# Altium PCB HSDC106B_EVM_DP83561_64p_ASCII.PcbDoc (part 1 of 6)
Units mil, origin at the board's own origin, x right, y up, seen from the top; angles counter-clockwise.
Board outline 8750.24 x 6394.7 mil, 6 copper layers (Top Layer, GND, SIG1, SIG2, GND1, Bottom Layer), stack 60.4 mil thick; 475 components, 330 nets, 1628 pads, 1086 vias.
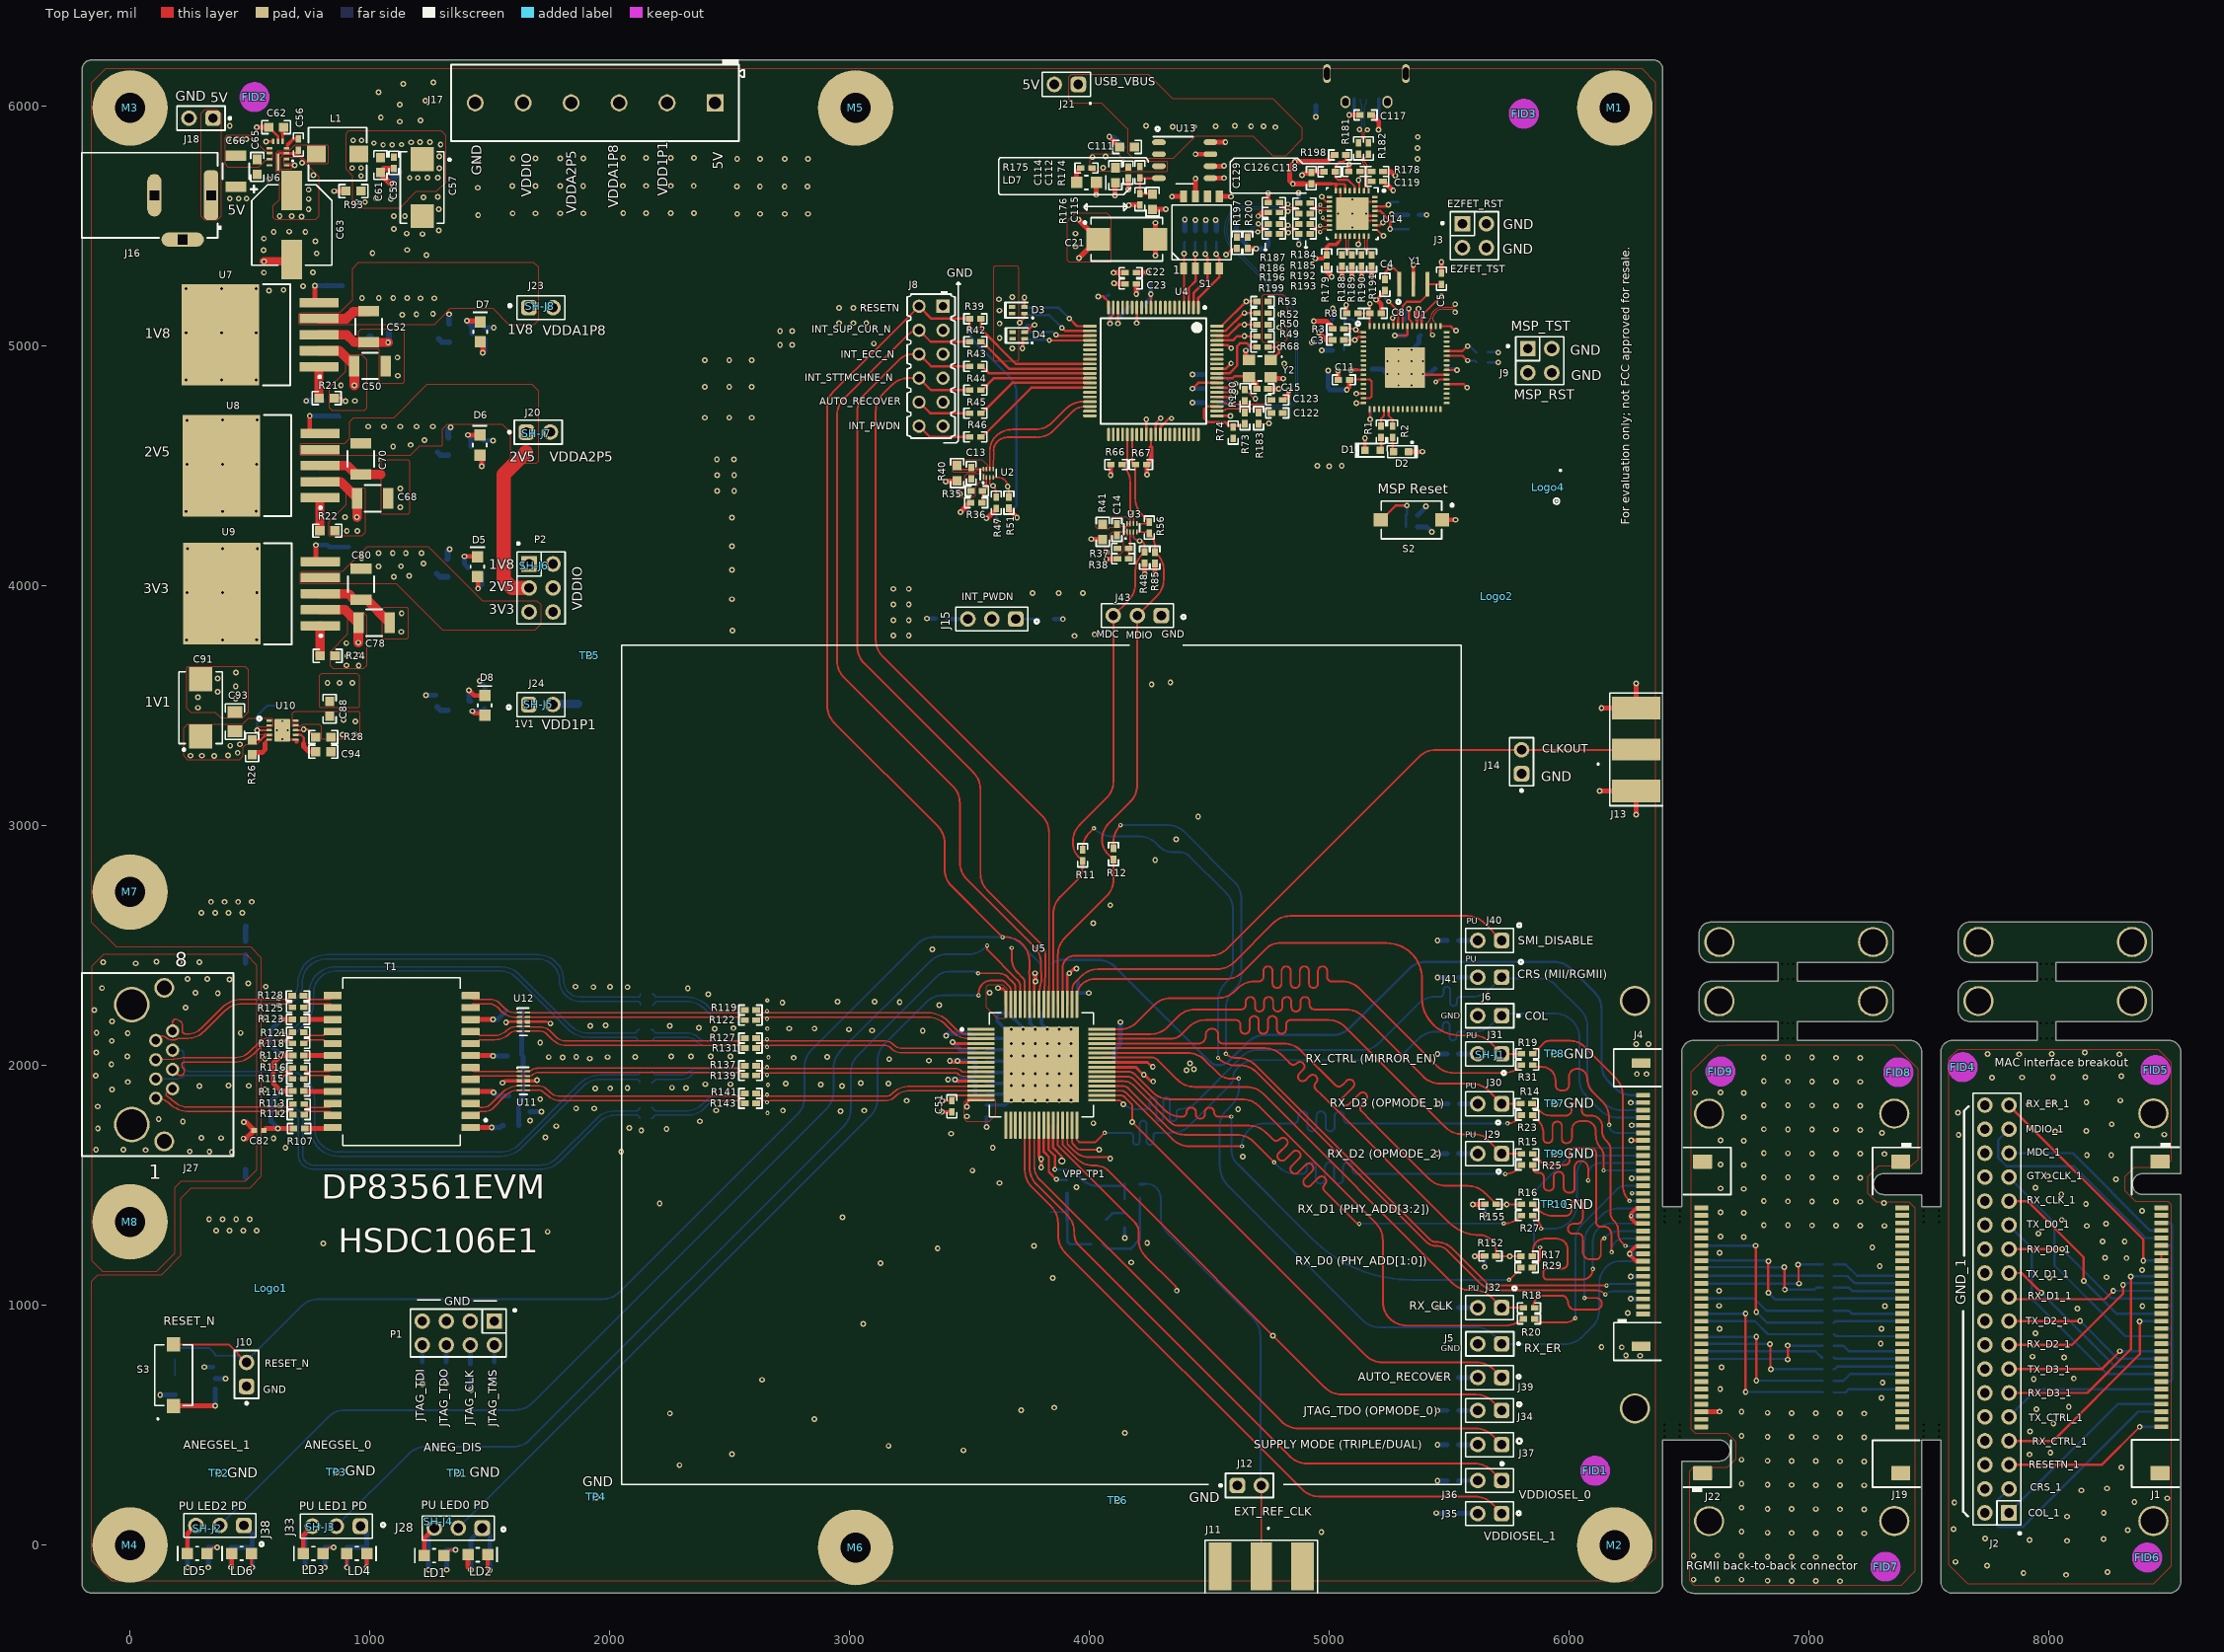
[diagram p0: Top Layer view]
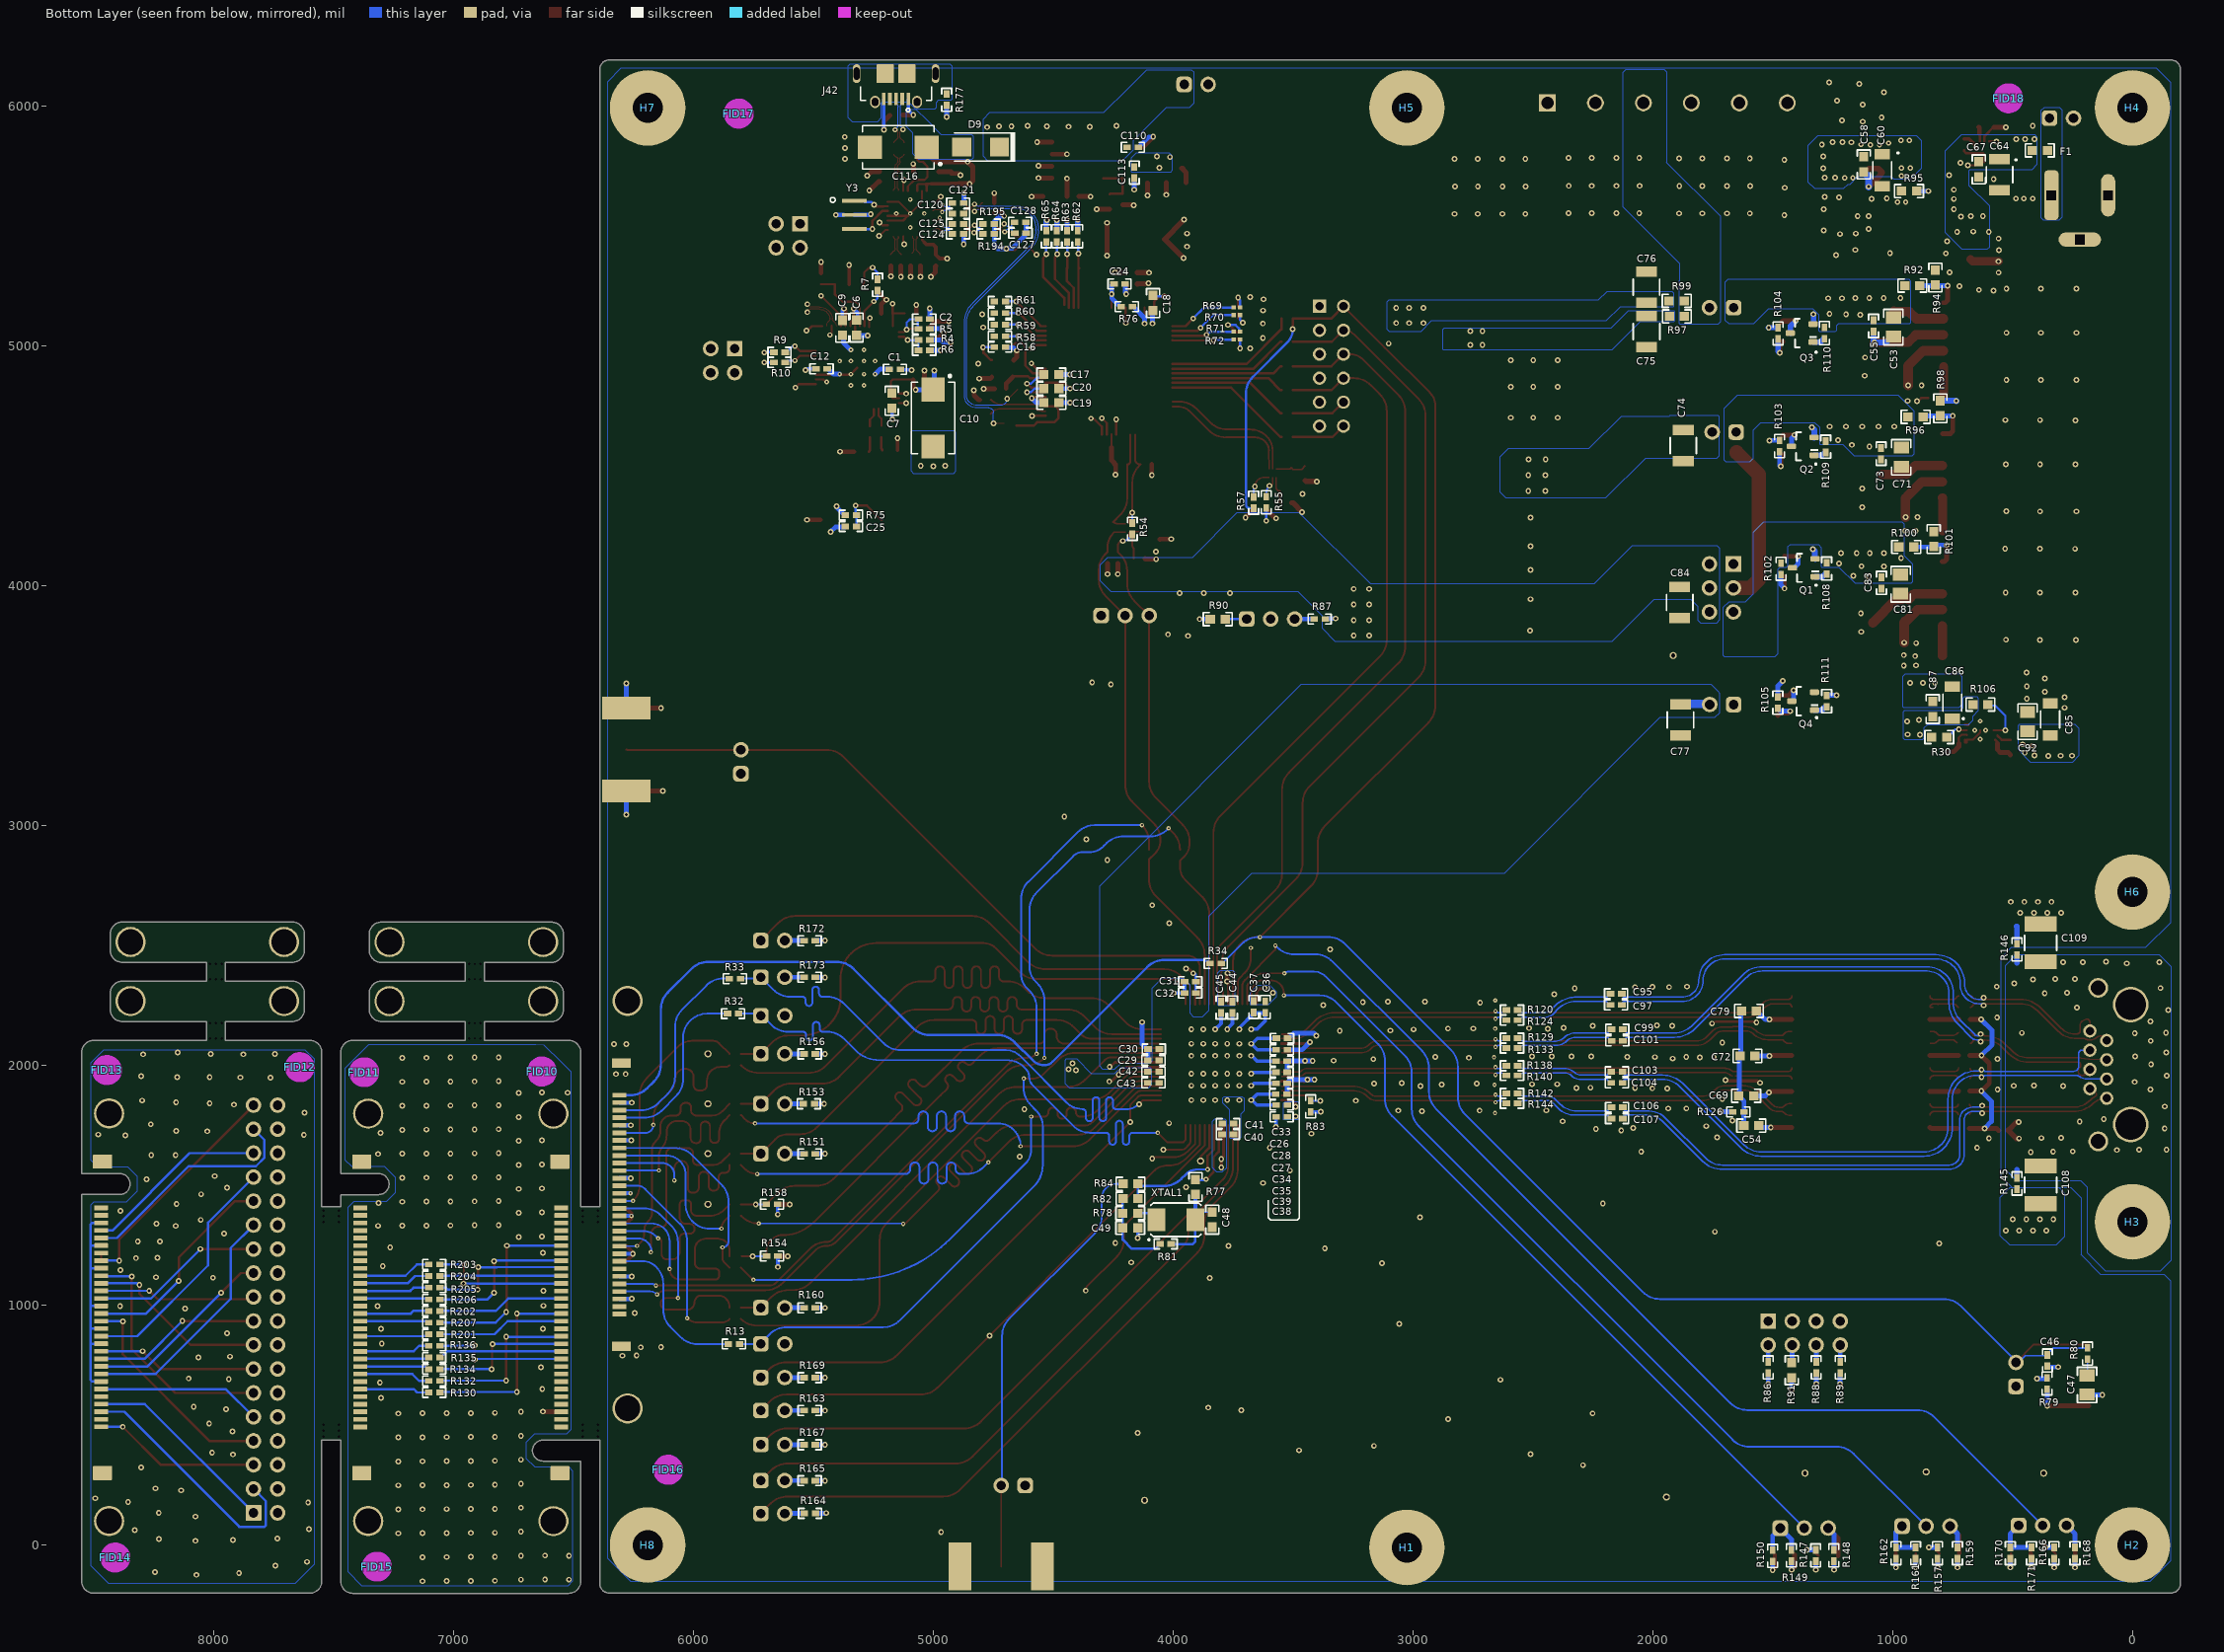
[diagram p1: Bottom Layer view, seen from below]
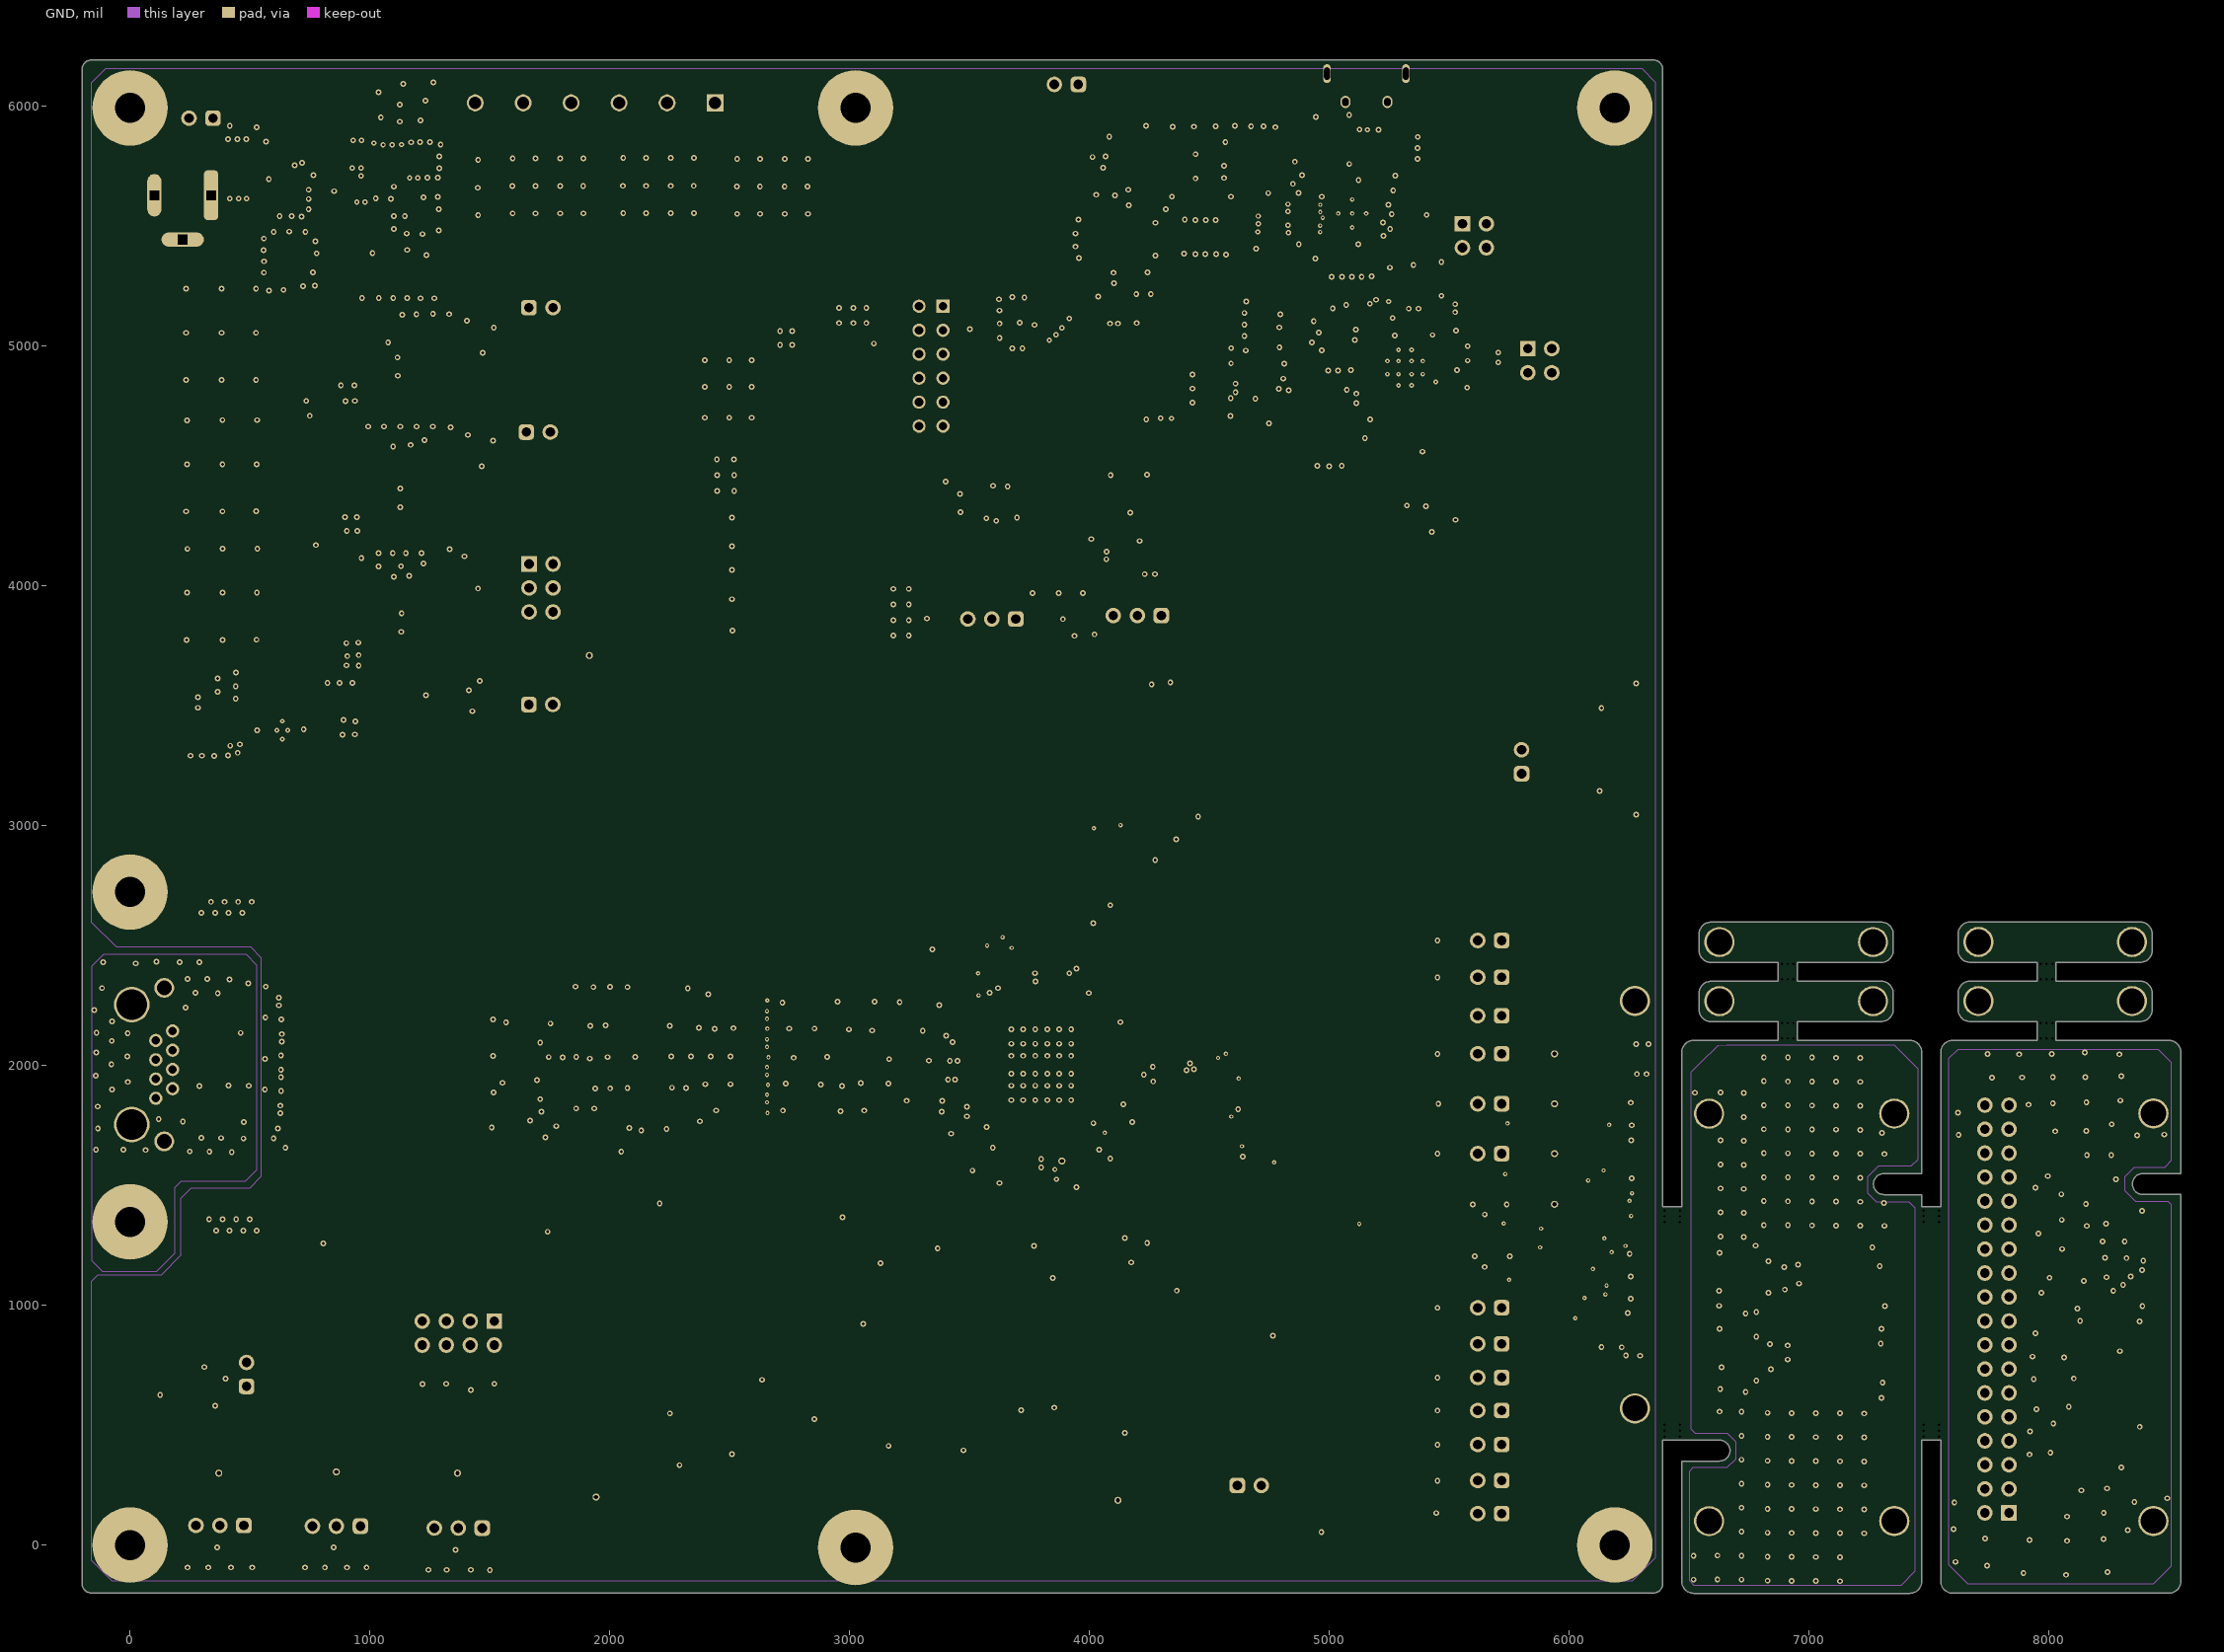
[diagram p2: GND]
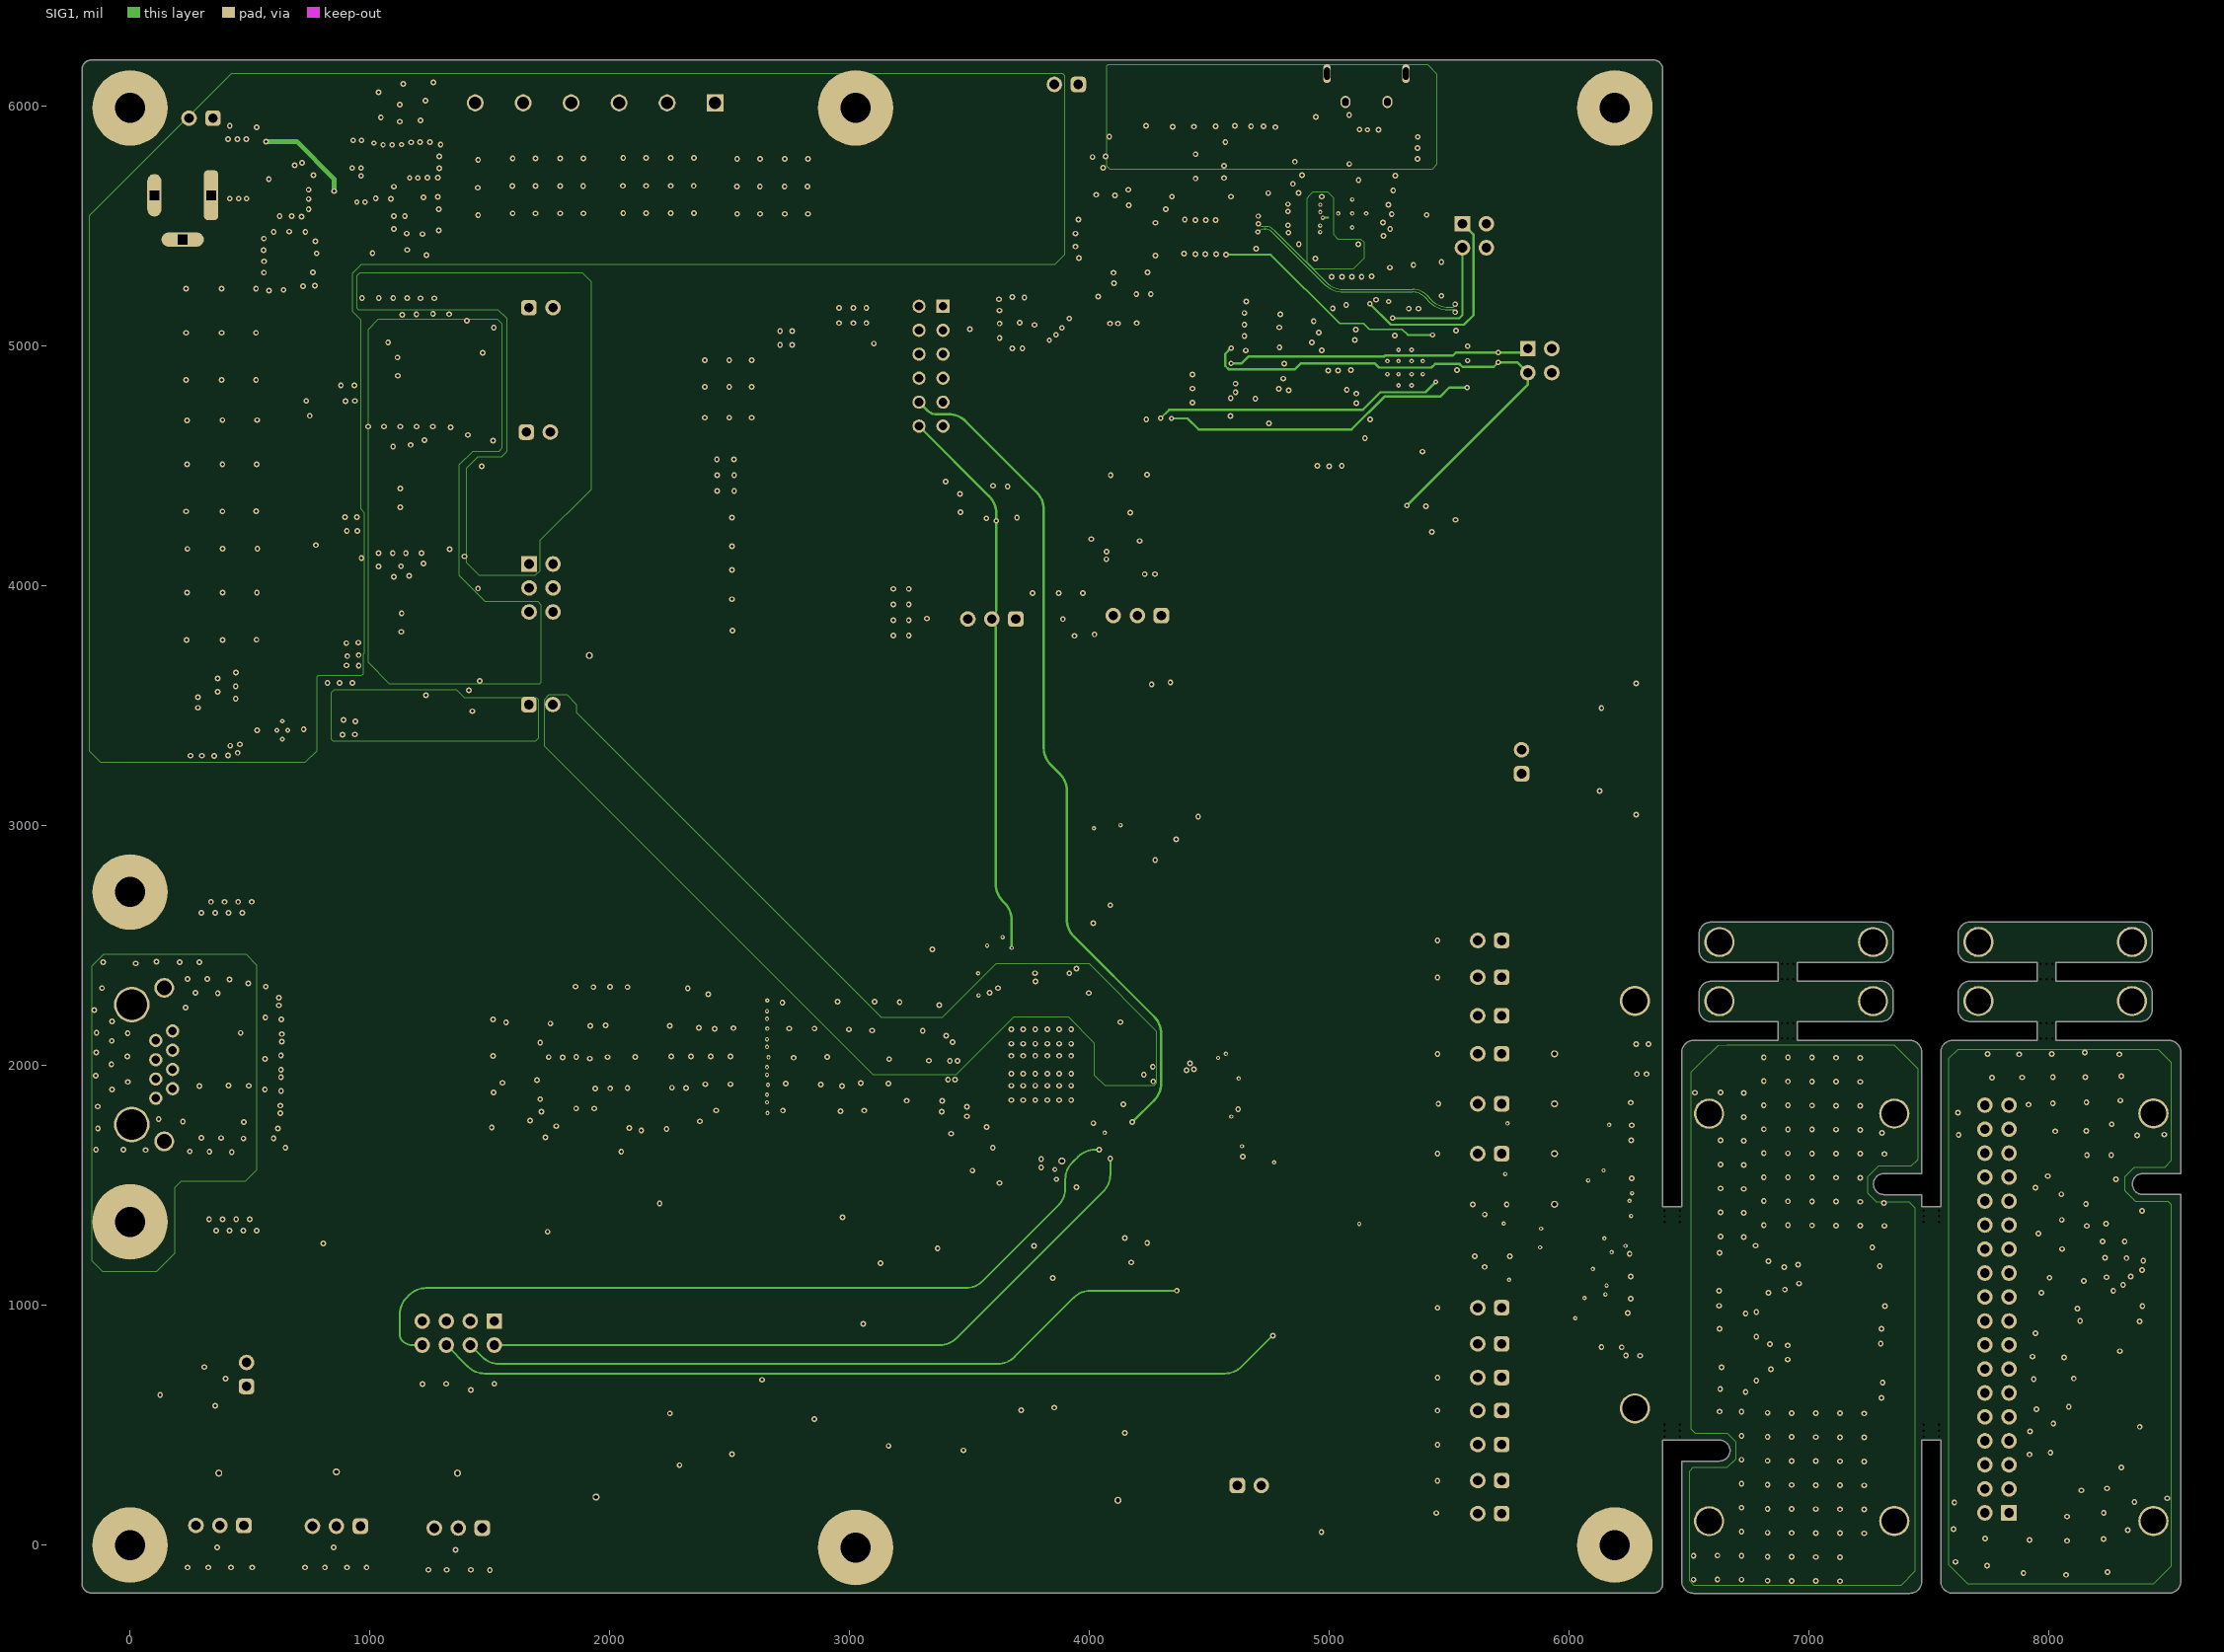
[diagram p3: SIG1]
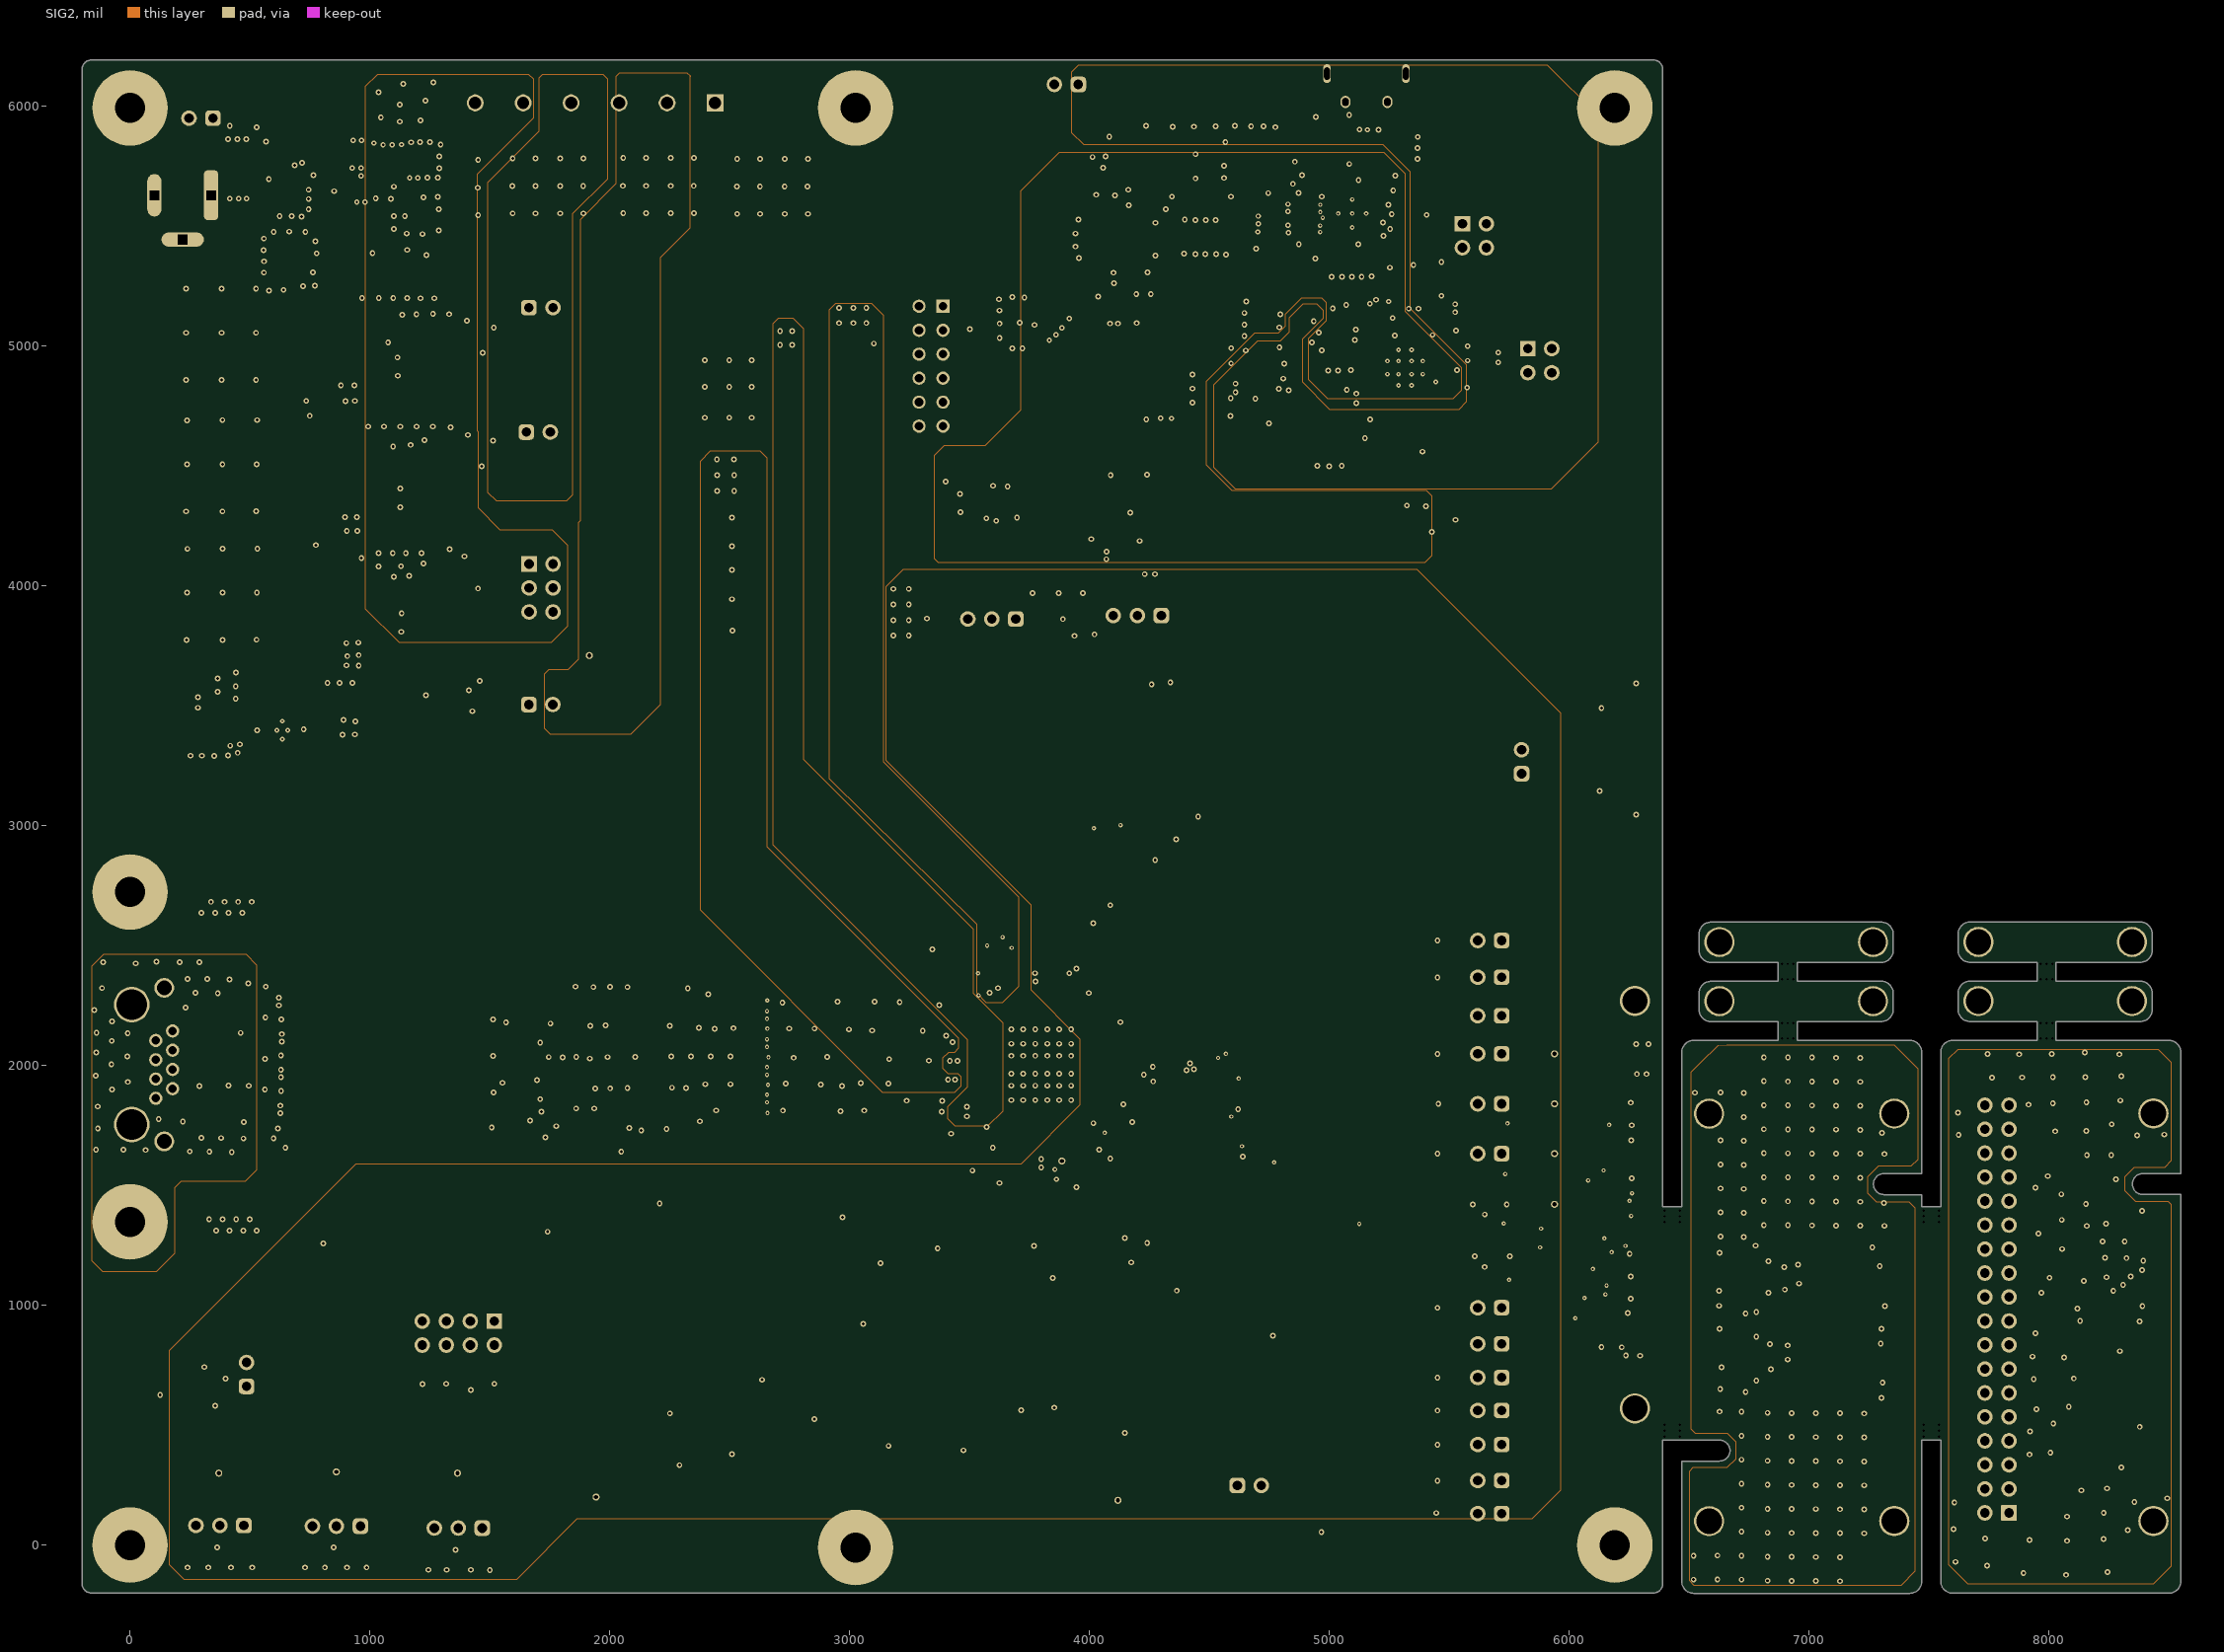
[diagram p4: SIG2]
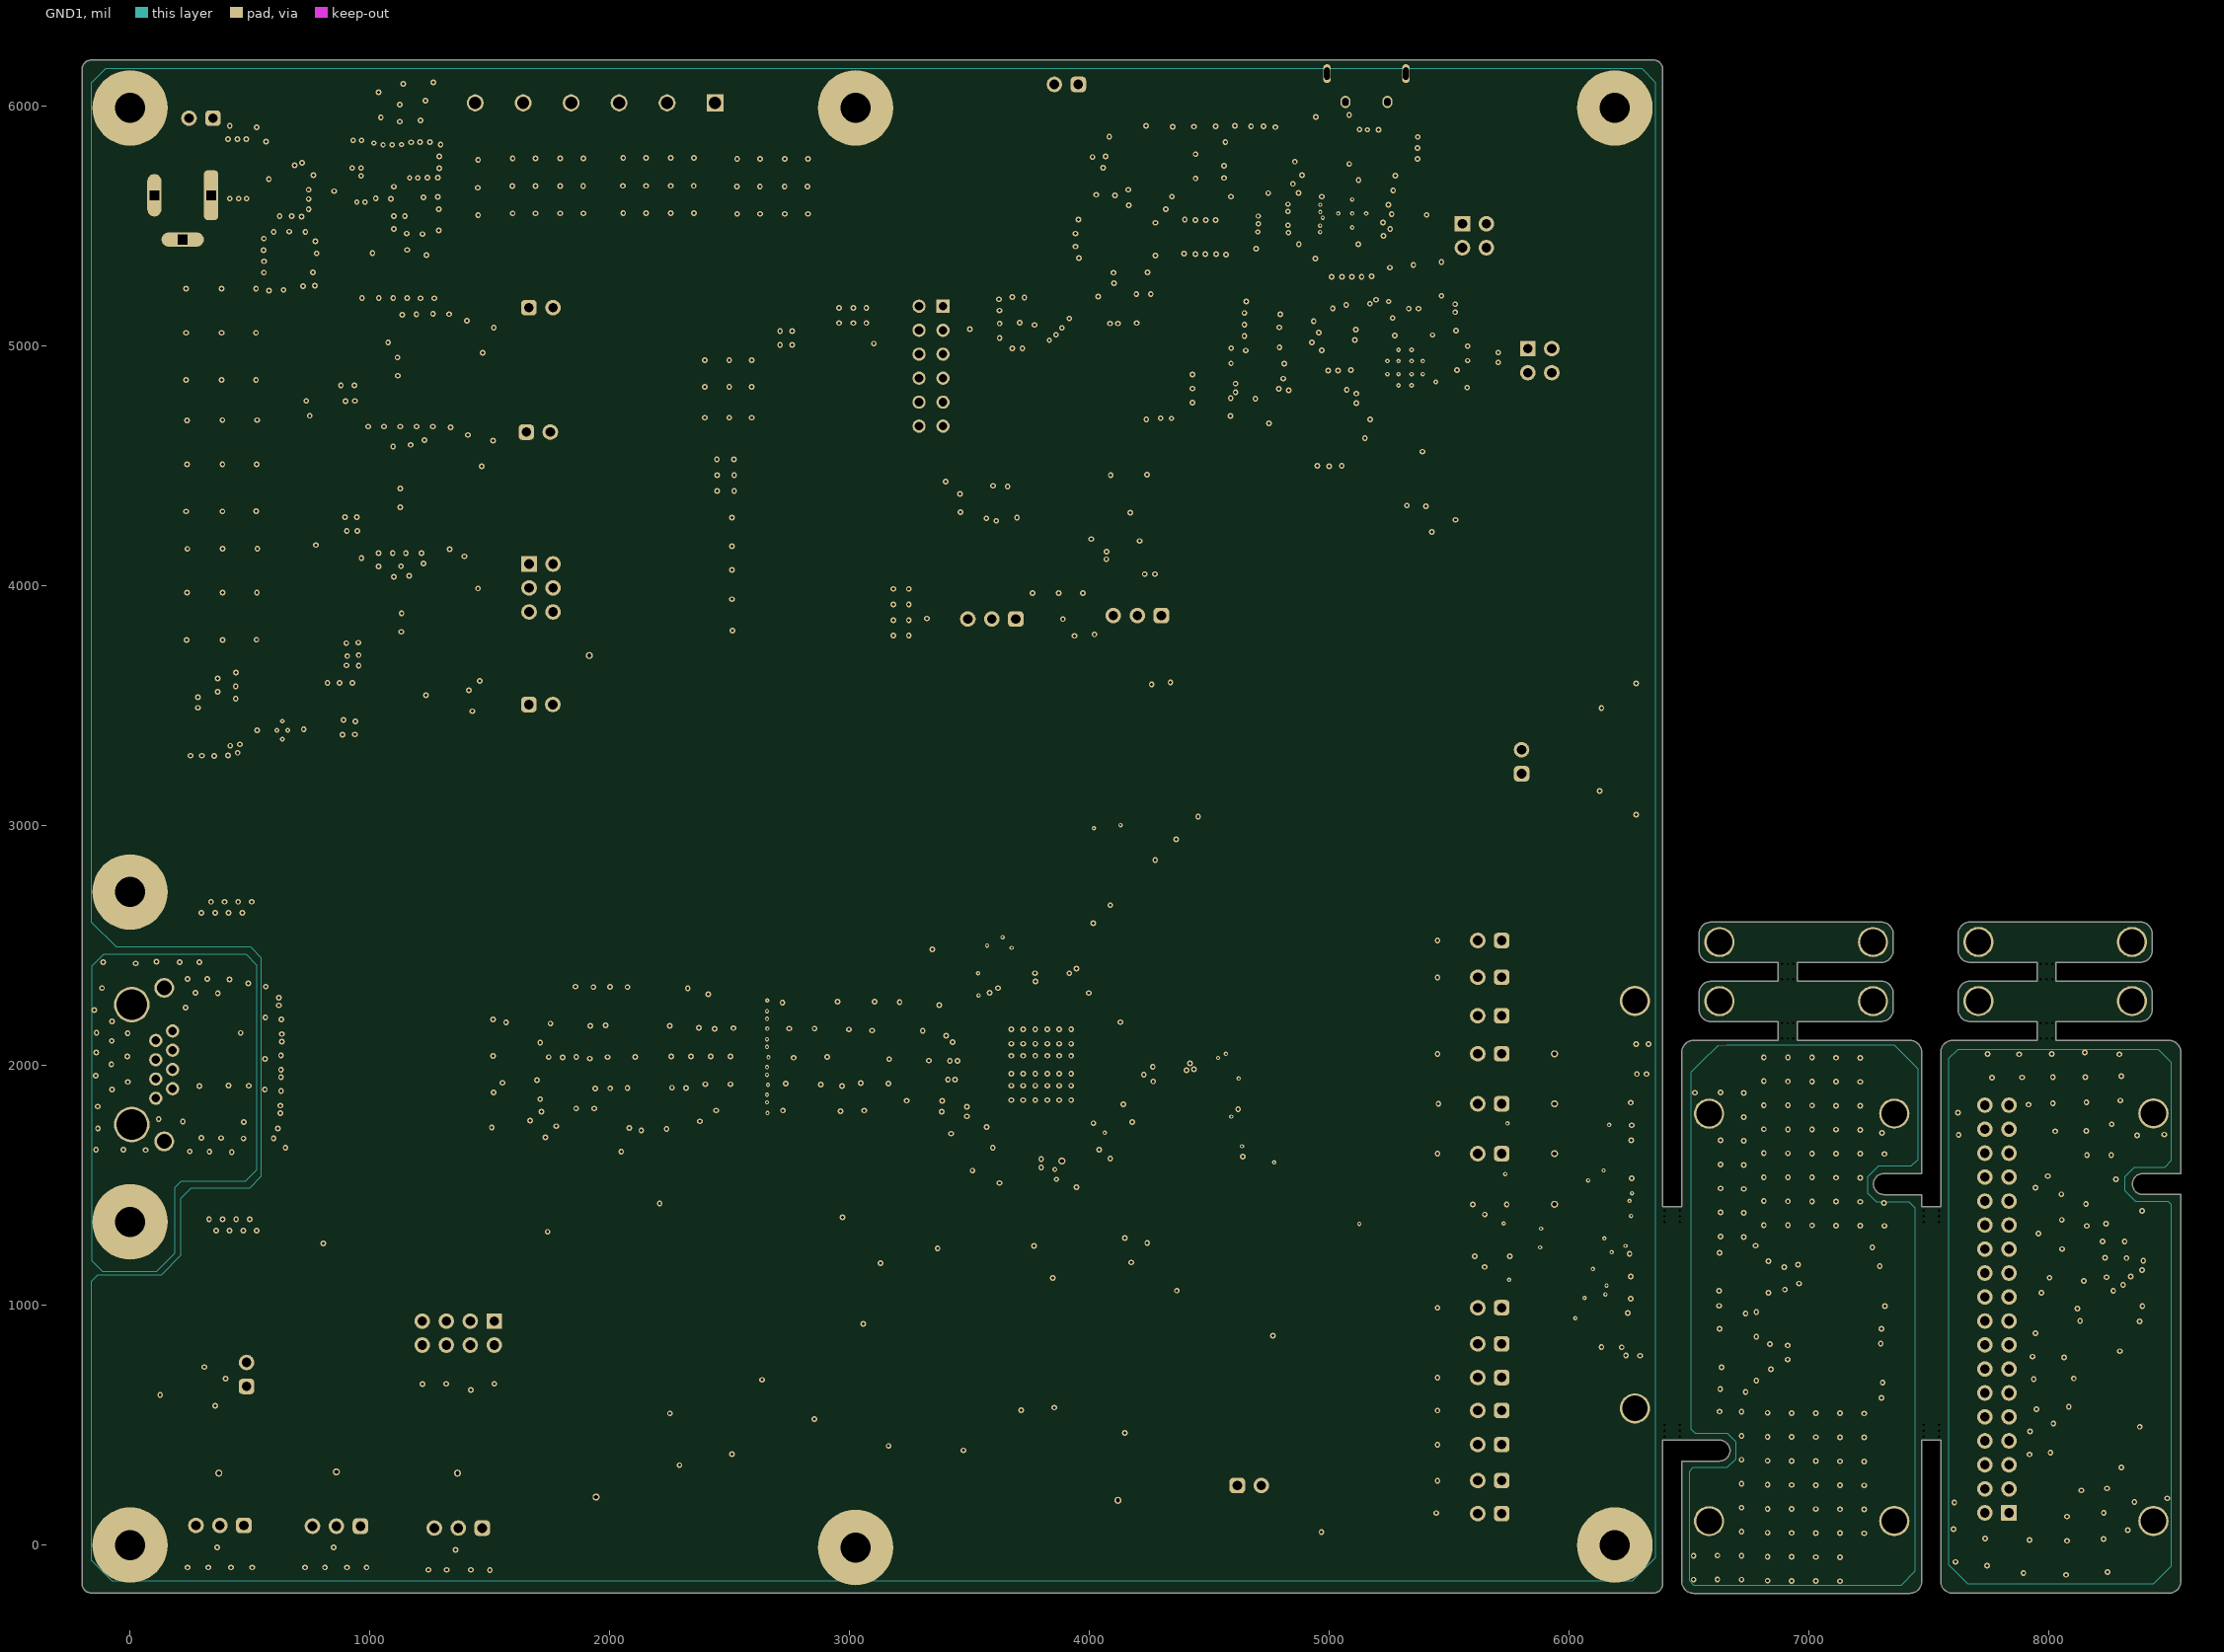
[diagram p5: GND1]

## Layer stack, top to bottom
Top Solder: solder mask 0.7, Solder Resist, Dk 3.5
Top Layer: signal copper 1.4
Dielectric 1: prepreg 5, FR-4 High Tg, Dk 4.6
GND: signal copper 1.4
Dielectric  2: core 5, FR-4 High Tg, Dk 4.6
SIG1: signal copper 1.4
Dielectric 3: prepreg 32, FR-4 High Tg, Dk 4.6
SIG2: signal copper 1.4
Dielectric 4: core 5, FR-4 High Tg, Dk 4.6
GND1: signal copper 1.4
Dielectric 5: prepreg 5, FR-4 High Tg, Dk 4.6
Bottom Layer: signal copper 1.4
Bottom Solder: solder mask 0.7, Solder Resist, Dk 3.5

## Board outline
6350.55,-200 ccw(c6350.55,-160) 6390.55,-160 6390.55,437.61 6391.84,437.8 6627.15,437.8 cw(c6627.15,394.35) 6670.6,394.35 6670.6,393.93 cw(c6627.06,393.93) 6627.06,350.39 6469.58,350.39 6469.29,297.49 6469.29,-151 ccw(c6519.29,-151) 6519.29,-201 7420.39,-201 ccw(c7420.39,-151) 7470.39,-151 7470.39,438.1 7549.42,438.1 7549.42,350.7 7549.13,297.8 7549.13,-150.69 ccw(c7599.13,-150.69) 7599.13,-200.69 8500.24,-200.69 ccw(c8500.24,-150.69) 8550.24,-150.69 8550.24,1462.03 8391.97,1462.03 cw(c8391.97,1505.48) 8348.52,1505.48 8348.52,1505.89 cw(c8392.06,1505.89) 8392.06,1549.43 8550.24,1549.43 8550.24,2054.91 ccw(c8500.24,2054.91) 8500.24,2104.91 8030.39,2104.91 8030.39,2183.65 8380.97,2183.65 8380.97,2183.78 ccw(c8380.97,2233.78) 8430.97,2233.78 8430.97,2301.78 ccw(c8380.97,2301.78) 8380.97,2351.78 8380.84,2351.65 8030.39,2351.65 8030.39,2430.39 8380.97,2430.39 8380.97,2430.52 ccw(c8380.97,2480.52) 8430.97,2480.52 8430.97,2548.52 ccw(c8380.97,2548.52) 8380.97,2598.52 8380.84,2598.39 7671.68,2598.39 ccw(c7671.68,2548.39) 7621.68,2548.39 7621.68,2480.39 ccw(c7671.68,2480.39) 7671.68,2430.39 7951.65,2430.39 7951.65,2351.65 7671.68,2351.65 ccw(c7671.68,2301.65) 7621.68,2301.65 7621.68,2233.65 ccw(c7671.68,2233.65) 7671.68,2183.65 7951.65,2183.65 7951.65,2104.91 7599.13,2104.91 ccw(c7599.13,2054.91) 7549.13,2054.91 7549.13,1410.74 7470.39,1410.74 7470.39,1461.72 7312.13,1461.72 cw(c7312.13,1505.17) 7268.68,1505.17 7268.68,1505.59 cw(c7312.22,1505.59) 7312.22,1549.13 7470.39,1549.13 7470.39,2054.61 ccw(c7420.39,2054.61) 7420.39,2104.61 6950.55,2104.61 6950.55,2183.35 7301.13,2183.35 7301.13,2183.47 ccw(c7301.13,2233.47) 7351.13,2233.47 7351.13,2301.47 ccw(c7301.13,2301.47) 7301.13,2351.47 7301,2351.35 6950.55,2351.35 6950.55,2430.09 7301.13,2430.09 7301.13,2430.21 ccw(c7301.13,2480.21) 7351.13,2480.21 7351.13,2548.21 ccw(c7301.13,2548.21) 7301.13,2598.21 7301,2598.09 6591.84,2598.09 ccw(c6591.84,2548.09) 6541.84,2548.09 6541.84,2480.09 ccw(c6591.84,2480.09) 6591.84,2430.09 6871.81,2430.09 6871.81,2351.35 6591.84,2351.35 ccw(c6591.84,2301.35) 6541.84,2301.35 6541.84,2233.35 ccw(c6591.84,2233.35) 6591.84,2183.35 6871.81,2183.35 6871.81,2104.61 6519.29,2104.61 ccw(c6519.29,2054.61) 6469.29,2054.61 6469.29,1410.43 6390.55,1410.43 6390.55,6153.7 ccw(c6350.55,6153.7) 6350.55,6193.7 -160,6193.7 ccw(c-160,6153.7) -200,6153.7 -200,-160 ccw(c-160,-160) -160,-200

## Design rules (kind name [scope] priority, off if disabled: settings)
AcuteAngle [All] p0: scope1count=1 scope1_0_kind=Board scope1_0_value=Board scope2count=1 scope2_0_kind=Board scope2_0_value=Board commentlength=0 minimum=4.50000000000000E+0001
AcuteAngle [All] p1: minimum=4.50000000000000E+0001 checktracksonly=FALSE
AssemblyTestPointUsage [All] p0: scope1count=1 scope1_0_kind=Board scope1_0_value=Board scope2count=1 scope2_0_kind=Board scope2_0_value=Board commentlength=0
AssemblyTestPointUsage [All] p1: valid=2
AssemblyTestpoint [All] p0: scope1count=1 scope1_0_kind=Board scope1_0_value=Board scope2count=1 scope2_0_kind=Board scope2_0_value=Board commentlength=0
BoardOutlineClearance "j11 AND J13" [All] p0 off: scope1count=1 scope1_0_kind=Board scope1_0_value=Board scope2count=1 scope2_0_kind=Board scope2_0_value=Board commentlength=143 gap=0 // Protel DXP Scope 1 Expression Was: InComponent('J11')OR InComponent('J13')or InComponent('J42')or InComponent('J4') or InComponent('FID10')
BoardOutlineClearance [All] p0 off: scope1count=1 scope1_0_kind=Board scope1_0_value=Board scope2count=1 scope2_0_kind=Board scope2_0_value=Board commentlength=157 gap=25 // Protel DXP Scope 1 Expression Was: OnCopper and Not InComponentClass('Logo') and not InComponentClass('FiducialMark') and not InRegion(1000,500,4000,800)
BoardOutlineClearance BoardOutlineClearance_Poly [All] p0 off: scope1count=1 scope1_0_kind=Board scope1_0_value=Board scope2count=1 scope2_0_kind=Board scope2_0_value=Board commentlength=57 gap=25 // Protel DXP Scope 1 Expression Was: OnCopper or IsPoly
BoardOutlineClearance BoardOutlineClearance_MountingHoles [All] p0: scope1count=1 scope1_0_kind=ComponentClass scope1_0_value=Mounting_hole scope2count=1 scope2_0_kind=Board scope2_0_value=Board commentlength=0 gap=40
BoardOutlineClearance "j11 AND J13" [InComponent('J11')OR InComponent('J13')or InComponent('J42')or InComponent('J4') or InComponent('FID10')] p1: gap=0 ignorepadtopadclearanceinfootprint=FALSE except(25: Fill-OutlineEdge Poly-OutlineEdge Poly-CavityEdge Poly-CutoutEdge Poly-SplitBarrior Poly-SplitContinuation)
BoardOutlineClearance BoardOutlineClearance_MountingHoles [InComponentClass('Mounting_hole')] p2: gap=40 ignorepadtopadclearanceinfootprint=FALSE
BoardOutlineClearance BoardOutlineClearance_Poly [OnCopper or IsPoly] p3: gap=25 ignorepadtopadclearanceinfootprint=FALSE except(0: Arc-OutlineEdge Arc-CutoutEdge Track-OutlineEdge Track-CutoutEdge SMDPad-CutoutEdge THPad-OutlineEdge THPad-CutoutEdge Via-OutlineEdge Via-CutoutEdge Fill-CutoutEdge Region-CutoutEdge Text-OutlineEdge Text-CutoutEdge; 20: SMDPad-OutlineEdge Poly-OutlineEdge)
BoardOutlineClearance [OnCopper and Not InComponentClass('Logo') and not InComponentClass('FiducialMark') and not InRegion(1000,500,4000,800)] p4: gap=25 ignorepadtopadclearanceinfootprint=FALSE except(0: SMDPad-CutoutEdge THPad-CutoutEdge)
Clearance 100 [All] p0 off: scope1count=1 scope1_0_kind=Board scope1_0_value=Board scope2count=1 scope2_0_kind=Board scope2_0_value=Board commentlength=48 gap=18 // Protel DXP Scope 2 Expression Was: InPolygon
Clearance U2/3 [All] p0 off: scope1count=1 scope1_0_kind=Board scope1_0_value=Board scope2count=1 scope2_0_kind=Board scope2_0_value=Board commentlength=64 gap=7.48 // Protel DXP Scope 2 Expression Was: IsTrack or IsPad or IsArc
Clearance "Clearance_RooM U7" [All] p0 off: scope1count=1 scope1_0_kind=Board scope1_0_value=Board scope2count=1 scope2_0_kind=Board scope2_0_value=Board commentlength=60 gap=5.9 // Protel DXP Scope 1 Expression Was: WithinRoom('Room U7')
Clearance J10_Pad [All] p0: scope1count=1 scope1_0_kind=PadClass scope1_0_value=J10 scope2count=1 scope2_0_kind=Board scope2_0_value=Board commentlength=0 gap=7.87
Clearance keepout_Pad [All] p0 off: scope1count=1 scope1_0_kind=Board scope1_0_value=Board scope2count=1 scope2_0_kind=ComponentClass scope2_0_value=Edge_connector commentlength=48 gap=0 // Protel DXP Scope 1 Expression Was: IsKeepOut
Clearance [All] p0: scope1count=1 scope1_0_kind=Board scope1_0_value=Board scope2count=1 scope2_0_kind=Board scope2_0_value=Board commentlength=0 gap=7.87
Clearance Clearance_FiducialMark [All] p0: scope1count=1 scope1_0_kind=ComponentClass scope1_0_value=Fiducial scope2count=1 scope2_0_kind=Board scope2_0_value=Board commentlength=0 gap=20
Clearance Clearance_Poly [All] p0 off: scope1count=1 scope1_0_kind=Board scope1_0_value=Board scope2count=1 scope2_0_kind=Board scope2_0_value=Board commentlength=48 gap=8 // Protel DXP Scope 1 Expression Was: InPolygon
Clearance Clearance_Keepouts [All] p0 off: scope1count=1 scope1_0_kind=Board scope1_0_value=Board scope2count=1 scope2_0_kind=Board scope2_0_value=Board commentlength=99 gap=0 // Protel DXP Scope 2 Expression Was: ((IsTrack Or IsArc) And Not InPoly) And IsFree and IsKeepOut
Clearance Mounting_hole [All] p0: scope1count=1 scope1_0_kind=PadClass scope1_0_value=MH scope2count=1 scope2_0_kind=Board scope2_0_value=Board commentlength=0 gap=40
Clearance Clearance_1 [All] p0 off: scope1count=1 scope1_0_kind=Board scope1_0_value=Board scope2count=1 scope2_0_kind=Board scope2_0_value=Board commentlength=45 gap=8 // Protel DXP Scope 2 Expression Was: inpoly
Clearance Gnd_MDI [All] p0 off: scope1count=1 scope1_0_kind=NetClass scope1_0_value=TD_x_gnd scope2count=1 scope2_0_kind=Board scope2_0_value=Board commentlength=73 gap=18 // Protel DXP Scope 2 Expression Was: InNet('GND') or InNet('RJ45_ERTH')
Clearance "50 OHM" [All] p0 off: scope1count=1 scope1_0_kind=NetClass scope1_0_value="50 OHM" scope2count=1 scope2_0_kind=Board scope2_0_value=Board commentlength=73 gap=8 // Protel DXP Scope 2 Expression Was: InNet('GND') or InNet('RJ45_ERTH')
Clearance 100 [InDifferentialPairClass('100 Ohm') OR InDifferentialPairClass('USB')OR InDifferentialPairClass('DP0') vs InPolygon] p1: gap=18 ignorepadtopadclearanceinfootprint=FALSE
Clearance U2/3 [IsTrack or IsPad or IsArc vs IsTrack or IsPad or IsArc] p2: gap=7.48 ignorepadtopadclearanceinfootprint=FALSE except(0: Arc-SMDPad; 4.6: Arc-Arc Arc-Track Arc-Via Track-Track Track-SMDPad Track-Via)
Clearance "Clearance_RooM U7" [WithinRoom('Room U7')] p3: gap=5.9 ignorepadtopadclearanceinfootprint=FALSE except(8: Arc-Fill Arc-Poly Arc-Region Track-Fill Track-Poly Track-Region SMDPad-Fill SMDPad-Poly SMDPad-Region THPad-Fill THPad-Poly THPad-Region Via-Fill Via-Poly Via-Region Fill-Fill Fill-Poly Fill-Region Poly-Poly Poly-Region Region-Region)
Clearance Gnd_MDI [InNetClass('TD_x_gnd') vs InNet('GND') or InNet('RJ45_ERTH')] p4: gap=18 ignorepadtopadclearanceinfootprint=FALSE except(5: SMDPad-SMDPad; 8: Arc-Arc Arc-Track Arc-SMDPad Arc-THPad Arc-Via Track-Track Track-SMDPad Track-THPad Track-Via; 15: SMDPad-Via)
Clearance "50 OHM" [InNetClass('50 OHM') vs InNet('GND') or InNet('RJ45_ERTH')] p5: gap=8 ignorepadtopadclearanceinfootprint=FALSE except(5: SMDPad-SMDPad; 7.78: SMDPad-Fill SMDPad-Poly SMDPad-Region; 7.87: Arc-Via Track-Via Via-Fill Via-Poly Via-Region; 15: SMDPad-Via; 18: SMDPad-THPad THPad-THPad THPad-Via THPad-Fill THPad-Poly THPad-Region Fill-Fill Fill-Poly Fill-Region Poly-Poly Poly-Region Region-Region; 20: Arc-Fill Arc-Poly Arc-Region Track-Fill Track-Poly Track-Region)
Clearance Clearance_Poly [InPolygon] p6: gap=8 ignorepadtopadclearanceinfootprint=FALSE except(0: Arc-Hole Track-Hole SMDPad-Hole THPad-Hole Via-Hole Fill-Hole Poly-Hole Region-Hole Text-Hole; 10: SMDPad-Poly; 15: THPad-Poly Fill-Poly; 20: Poly-Poly)
Clearance J10_Pad [InPadClass('J10')] p7: gap=7.87 ignorepadtopadclearanceinfootprint=FALSE except(10: Arc-Poly Track-Poly SMDPad-Poly THPad-Poly Via-Poly Fill-Poly Poly-Poly)
Clearance keepout_Pad [IsKeepOut vs InComponentClass('Edge_connector')] p8: gap=0 ignorepadtopadclearanceinfootprint=TRUE
Clearance Mounting_hole [InPadClass('MH')] p9: gap=40 ignorepadtopadclearanceinfootprint=TRUE
Clearance Clearance_FiducialMark [InComponentClass('Fiducial')] p10: gap=20 ignorepadtopadclearanceinfootprint=FALSE
Clearance Clearance_1 [isvia vs inpoly] p11: gap=8 ignorepadtopadclearanceinfootprint=TRUE
Clearance Clearance_Keepouts [((IsTrack Or IsArc) And Not InPoly) And IsFree and IsKeepOut vs ((IsTrack Or IsArc) And Not InPoly) And IsFree and IsKeepOut] p12: gap=0 ignorepadtopadclearanceinfootprint=FALSE
Clearance [All] p13: gap=7.87 ignorepadtopadclearanceinfootprint=TRUE except(0: Arc-SMDPad Arc-Hole Track-Hole SMDPad-Hole THPad-Hole Via-Hole Fill-Hole Poly-Hole Region-Hole Text-Hole; 4.6: Arc-Track Arc-Via Track-Track Track-SMDPad Track-Via; 7.6: SMDPad-SMDPad; 15: Poly-Region; 20: Arc-Poly Track-Poly Poly-Poly)
ComponentClearance ComponentClearance_jumper [All] p0: scope1count=1 scope1_0_kind=Board scope1_0_value=Board scope2count=1 scope2_0_kind=Footprint scope2_0_value=Harwin_M7582-05 commentlength=0 gap=0 collisioncheckmode=3
ComponentClearance J10_H1 [All] p0 off: scope1count=1 scope1_0_kind=Board scope1_0_value=Board scope2count=1 scope2_0_kind=Board scope2_0_value=Board commentlength=124 gap=0 collisioncheckmode=3 // Protel DXP Scope 1 Expression Was: InComponentClass('SFP')or InComponent('J2') or InComponent('J4')or InComponent('J22')
ComponentClearance ComponentClearance_Fiducial [All] p0: scope1count=1 scope1_0_kind=Component scope1_0_value=H1 scope2count=1 scope2_0_kind=ComponentClass scope2_0_value=FiducialMark commentlength=0 gap=0 collisioncheckmode=3
ComponentClearance ComponentClearance_Fiber [All] p0: scope1count=1 scope1_0_kind=Component scope1_0_value=J3 scope2count=1 scope2_0_kind=Component scope2_0_value=H1 commentlength=0 gap=0 collisioncheckmode=3
ComponentClearance [All] p0: scope1count=1 scope1_0_kind=Board scope1_0_value=Board scope2count=1 scope2_0_kind=Board scope2_0_value=Board commentlength=0 gap=10 collisioncheckmode=3
ComponentClearance ComponentClearance_THtoTH [All] p0 off: scope1count=1 scope1_0_kind=Board scope1_0_value=Board scope2count=1 scope2_0_kind=Board scope2_0_value=Board commentlength=54 gap=30 collisioncheckmode=3 // Protel DXP Scope 2 Expression Was: IsThruComponent
ComponentClearance ComponentClearance_THtoSMT [All] p0 off: scope1count=1 scope1_0_kind=Board scope1_0_value=Board scope2count=1 scope2_0_kind=Board scope2_0_value=Board commentlength=53 gap=10 collisioncheckmode=3 // Protel DXP Scope 2 Expression Was: IsSMTComponent
ComponentClearance ComponentClearance_SmallPassives [All] p0 off: scope1count=1 scope1_0_kind=Board scope1_0_value=Board scope2count=1 scope2_0_kind=Board scope2_0_value=Board commentlength=508 gap=10 collisioncheckmode=3 // Protel DXP Scope 2 Expression Was: HasFootprint('0201*') or HasFootprint('0402*') or HasFootprint('0508') or HasFootprint('0603*') or HasFootprint('0612') or HasFootprint('0805*') or HasFootprint('0815*') or HasFootprint('0830*') or HasFootprint('1206*') or HasFootprint('1210*') or HasFootprint('1808*') or HasFootprint('1812*') or HasFootprint('1825*') or HasFootprint('2010*') or HasFootprint('2220*') or HasFootprint('2225*') or HasFootprint('2512*') or HasFootprint('2728*') or HasFootprint('3518*')
ComponentClearance ComponentClearance_MountingHoles [All] p0: scope1count=1 scope1_0_kind=ComponentClass scope1_0_value="Mounting Holes" scope2count=1 scope2_0_kind=Board scope2_0_value=Board commentlength=0 gap=250 collisioncheckmode=3
ComponentClearance ComponentClearance_ScrewToNut [All] p0 off: scope1count=1 scope1_0_kind=Board scope1_0_value=Board scope2count=1 scope2_0_kind=Board scope2_0_value=Board commentlength=71 gap=5 collisioncheckmode=3 // Protel DXP Scope 2 Expression Was: (HasFootprint('Keystone_1902C'))
ComponentClearance ComponentClearance_Logo [All] p0: scope1count=1 scope1_0_kind=ComponentClass scope1_0_value=Logo scope2count=1 scope2_0_kind=Board scope2_0_value=Board commentlength=0 gap=50 collisioncheckmode=3
ComponentClearance ComponentClearance_Shunt [All] p0 off: scope1count=1 scope1_0_kind=Board scope1_0_value=Board scope2count=1 scope2_0_kind=ComponentClass scope2_0_value=Shunt commentlength=87 gap=0 collisioncheckmode=3 // Protel DXP Scope 1 Expression Was: InComponentClass('Header') OR InComponent('J30')
ComponentClearance ComponentClearance_MountingHoles_FiducialMarks [All] p0: scope1count=1 scope1_0_kind=ComponentClass scope1_0_value="Mounting Holes" scope2count=1 scope2_0_kind=ComponentClass scope2_0_value=FiducialMark commentlength=0 gap=50 collisioncheckmode=3
ComponentClearance ComponentClearance_jumper [All vs HasFootprint('Harwin_M7582-05')] p1: gap=0 collisioncheckmode=3 verticalgap=0 showdistances=FALSE
ComponentClearance J10_H1 [InComponentClass('SFP')or InComponent('J2') or InComponent('J4')or InComponent('J22')] p2: gap=0 collisioncheckmode=3 verticalgap=0 showdistances=FALSE
ComponentClearance ComponentClearance_Shunt [InComponentClass('Header') OR InComponent('J30') vs InComponentClass('Shunt')] p3: gap=0 collisioncheckmode=3 verticalgap=0 showdistances=FALSE
ComponentClearance ComponentClearance_Fiducial [InComponent('H1') vs InComponentClass('FiducialMark')] p4: gap=0 collisioncheckmode=3 verticalgap=0 showdistances=FALSE
ComponentClearance ComponentClearance_Fiber [InComponent('J3') vs InComponent('H1')] p5: gap=0 collisioncheckmode=3 verticalgap=0 showdistances=FALSE
ComponentClearance ComponentClearance_MountingHoles_FiducialMarks [InComponentClass('Mounting Holes') vs InComponentClass('FiducialMark')] p6: gap=50 collisioncheckmode=3 verticalgap=10 showdistances=FALSE
ComponentClearance ComponentClearance_Logo [InComponentClass('Logo')] p7: gap=50 collisioncheckmode=3 verticalgap=10 showdistances=FALSE
ComponentClearance ComponentClearance_ScrewToNut [(HasFootprint('NY PMS 440 0025 PH')) vs (HasFootprint('Keystone_1902C'))] p8: gap=5 collisioncheckmode=3 verticalgap=10 showdistances=FALSE
ComponentClearance ComponentClearance_MountingHoles [InComponentClass('Mounting Holes')] p9: gap=250 collisioncheckmode=3 verticalgap=100000 showdistances=FALSE
ComponentClearance ComponentClearance_SmallPassives [HasFootprint('0201*') or HasFootprint('0402*') or HasFootprint('0508') or HasFootprint('0603*') or HasFootprint('0612') or HasFootprint('0805*') or HasFootprint('0815*') or HasFootprint('0830*') or HasFootprint('1206*') or HasFootprint('1210*') or HasFootprint('1808*') or HasFootprint('1812*') or HasFootprint('1825*') or HasFootprint('2010*') or HasFootprint('2220*') or HasFootprint('2225*') or HasFootprint('2512*') or HasFootprint('2728*') or HasFootprint('3518*') vs HasFootprint('0201*') or HasFootprint('0402*') or HasFootprint('0508') or HasFootprint('0603*') or HasFootprint('0612') or HasFootprint('0805*') or HasFootprint('0815*') or HasFootprint('0830*') or HasFootprint('1206*') or HasFootprint('1210*') or HasFootprint('1808*') or HasFootprint('1812*') or HasFootprint('1825*') or HasFootprint('2010*') or HasFootprint('2220*') or HasFootprint('2225*') or HasFootprint('2512*') or HasFootprint('2728*') or HasFootprint('3518*')] p10: gap=10 collisioncheckmode=3 verticalgap=10 showdistances=FALSE
ComponentClearance ComponentClearance_THtoSMT [IsThruComponent vs IsSMTComponent] p11: gap=10 collisioncheckmode=3 verticalgap=10 showdistances=FALSE
ComponentClearance ComponentClearance_THtoTH [IsThruComponent vs IsThruComponent] p12: gap=30 collisioncheckmode=3 verticalgap=30 showdistances=FALSE
ComponentClearance [All] p13: gap=10 collisioncheckmode=3 verticalgap=10 showdistances=FALSE
DiffPairsRouting "100 Ohm" [All] p0 off: scope1count=1 scope1_0_kind=Board scope1_0_value=Board scope2count=1 scope2_0_kind=Board scope2_0_value=Board commentlength=73 // Protel DXP Scope 1 Expression Was: InDifferentialPairClass('100 Ohm')
DiffPairsRouting USB_1 [All] p0 off: scope1count=1 scope1_0_kind=Board scope1_0_value=Board scope2count=1 scope2_0_kind=Board scope2_0_value=Board commentlength=69 // Protel DXP Scope 1 Expression Was: InDifferentialPairClass('USB')
DiffPairsRouting USB_1 [InDifferentialPairClass('USB')] p1: maxlimit=6.1 minlimit=4.6 mostfreqgap=6.1 toplayer_maxgap=4.6 toplayer_prefgap=4.6 toplayer_minwidth=5 toplayer_maxwidth=5 toplayer_prefwidth=5 midlayer1_mingap=6.1 midlayer1_minwidth=5 midlayer1_maxwidth=5 midlayer1_prefwidth=5 midlayer2_mingap=6.1 midlayer2_minwidth=5 midlayer2_maxwidth=5 midlayer2_prefwidth=5 midlayer3_mingap=6.1 midlayer3_minwidth=5 midlayer3_maxwidth=5 midlayer3_prefwidth=5 midlayer6_mingap=6.1 midlayer6_minwidth=5 midlayer6_maxwidth=5 midlayer6_prefwidth=5 bottomlayer_maxgap=4.6 bottomlayer_prefgap=4.6 bottomlayer_minwidth=5 bottomlayer_maxwidth=5 bottomlayer_prefwidth=5 maxuncoupledlength=1000
DiffPairsRouting "100 Ohm" [InDifferentialPairClass('100 Ohm')] p2: maxlimit=12 minlimit=11 mostfreqgap=12 toplayer_mingap=12 toplayer_minwidth=6 toplayer_maxwidth=6 toplayer_prefwidth=6 midlayer1_mingap=12 midlayer1_minwidth=6 midlayer1_maxwidth=6 midlayer1_prefwidth=6 midlayer2_maxgap=11 midlayer2_prefgap=11 midlayer2_minwidth=6 midlayer2_maxwidth=6 midlayer2_prefwidth=6 midlayer3_maxgap=11 midlayer3_prefgap=11 midlayer3_minwidth=6 midlayer3_maxwidth=6 midlayer3_prefwidth=6 midlayer6_mingap=12 midlayer6_minwidth=6 midlayer6_maxwidth=6 midlayer6_prefwidth=6 bottomlayer_mingap=12 bottomlayer_minwidth=6 bottomlayer_maxwidth=6 bottomlayer_prefwidth=6 maxuncoupledlength=500
FabricationTestPointUsage TestPointUsage [All] p0: scope1count=1 scope1_0_kind=Board scope1_0_value=Board scope2count=1 scope2_0_kind=Board scope2_0_value=Board commentlength=0 valid=2 allowmultiple=FALSE
FabricationTestPointUsage TestPointUsage [All] p1: valid=2 allowmultiple=FALSE
FabricationTestpoint Testpoint [All] p0: scope1count=1 scope1_0_kind=Board scope1_0_value=Board scope2count=1 scope2_0_kind=Board scope2_0_value=Board commentlength=0 side=3 testpointundercomponent=TRUE minsize=40 maxsize=100 preferedsize=60 minholesize=0 maxholesize=40 preferedholesize=32 testpointgrid=1
FabricationTestpoint Testpoint [All] p1: side=3 testpointundercomponent=TRUE minsize=40 maxsize=100 preferedsize=60 minholesize=0 maxholesize=40 preferedholesize=32 testpointgrid=1 allowsidetop=TRUE allowsidebottom=TRUE usegrid=TRUE gridtolerance=0.01
FanoutControl Fanout_Small [All] p0 off: scope1count=1 scope1_0_kind=Board scope1_0_value=Board scope2count=1 scope2_0_kind=Board scope2_0_value=Board commentlength=84 // Protel DXP Scope 1 Expression Was: (CompPinCount < 5)   Fanout_Small (Default Rule)
FanoutControl Fanout_Default [All] p0: scope1count=1 scope1_0_kind=Board scope1_0_value=Board scope2count=1 scope2_0_kind=Board scope2_0_value=Board commentlength=30 // Fanout_Default (Default Rule)
FanoutControl Fanout_SOIC [All] p0 off: scope1count=1 scope1_0_kind=Board scope1_0_value=Board scope2count=1 scope2_0_kind=Board scope2_0_value=Board commentlength=71 // Protel DXP Scope 1 Expression Was: IsSOIC   Fanout_SOIC (Default Rule)
FanoutControl Fanout_BGA [All] p0 off: scope1count=1 scope1_0_kind=Board scope1_0_value=Board scope2count=1 scope2_0_kind=Board scope2_0_value=Board commentlength=69 // Protel DXP Scope 1 Expression Was: IsBGA   Fanout_BGA (Default Rule)
FanoutControl Fanout_LCC [All] p0 off: scope1count=1 scope1_0_kind=Board scope1_0_value=Board scope2count=1 scope2_0_kind=Board scope2_0_value=Board commentlength=69 // Protel DXP Scope 1 Expression Was: IsLCC   Fanout_LCC (Default Rule)
FanoutControl Fanout_LCC [IsLCC] p1: bgadir=Out bgaviamode=Centered fanoutstyle=Auto fanoutdirection=Alternating viagrid=1 // Fanout_LCC (Default Rule)
FanoutControl Fanout_BGA [IsBGA] p2: bgadir=Out bgaviamode=Centered fanoutstyle=Auto fanoutdirection=Alternating viagrid=1 // Fanout_BGA (Default Rule)
FanoutControl Fanout_Default [All] p4: bgadir=Out bgaviamode=Centered fanoutstyle=Auto fanoutdirection=Alternating viagrid=1 // Fanout_Default (Default Rule)
FanoutControl Fanout_Small [(CompPinCount < 5)] p5: bgadir=Out bgaviamode=Centered fanoutstyle=Auto fanoutdirection=OutThenIn viagrid=1 // Fanout_Small (Default Rule)
Height [All] p0: scope1count=1 scope1_0_kind=Board scope1_0_value=Board scope2count=1 scope2_0_kind=Board scope2_0_value=Board commentlength=0
HoleSize [All] p0: scope1count=1 scope1_0_kind=Board scope1_0_value=Board scope2count=1 scope2_0_kind=Board scope2_0_value=Board commentlength=0 absolutevalues=TRUE maxlimit=251 minlimit=7.87 maxpercent=80.000 minpercent=20.000
HoleSize [All] p1: absolutevalues=TRUE maxlimit=251 minlimit=7.87 maxpercent=80.000 minpercent=20.000
HoleToHoleClearance [All] p0: scope1count=1 scope1_0_kind=Board scope1_0_value=Board scope2count=1 scope2_0_kind=Board scope2_0_value=Board commentlength=0
LayerPairs [All] p0: scope1count=1 scope1_0_kind=Board scope1_0_value=Board scope2count=1 scope2_0_kind=Board scope2_0_value=Board commentlength=0 enforce=TRUE
MatchedLengths TX [All] p0: scope1count=1 scope1_0_kind=NetClass scope1_0_value=TX_SIGNAL scope2count=1 scope2_0_kind=Board scope2_0_value=Board commentlength=0 tolerance=10 amplitude=200 gap=20 style=90-Degree
MatchedLengths RX [All] p0: scope1count=1 scope1_0_kind=NetClass scope1_0_value=RX_SIGNAL scope2count=1 scope2_0_kind=Board scope2_0_value=Board commentlength=0 tolerance=10 amplitude=200 gap=20 style=90-Degree
MatchedLengths MatchedLengths_RGMIIRX [All] p0: scope1count=1 scope1_0_kind=NetClass scope1_0_value=RGMII_RX scope2count=1 scope2_0_kind=Board scope2_0_value=Board commentlength=0 tolerance=200 amplitude=200 gap=20 style=90-Degree
MatchedLengths MatchedLengths_RGMIITX [All] p0: scope1count=1 scope1_0_kind=NetClass scope1_0_value=RGMII_TX scope2count=1 scope2_0_kind=Board scope2_0_value=Board commentlength=0 tolerance=150 amplitude=200 gap=20 style=90-Degree
MatchedLengths RX_Break [All] p0: scope1count=1 scope1_0_kind=NetClass scope1_0_value=RX_Break_out scope2count=1 scope2_0_kind=Board scope2_0_value=Board commentlength=0 tolerance=100 amplitude=200 gap=20 style=90-Degree
MatchedLengths TX_Break [All] p0: scope1count=1 scope1_0_kind=NetClass scope1_0_value=TX_Break_out scope2count=1 scope2_0_kind=Board scope2_0_value=Board commentlength=0 tolerance=100 amplitude=200 gap=20 style=90-Degree
MatchedLengths TX_CS [All] p0: scope1count=1 scope1_0_kind=NetClass scope1_0_value=TX_CS scope2count=1 scope2_0_kind=Board scope2_0_value=Board commentlength=0 tolerance=30 amplitude=200 gap=20 style=90-Degree
MatchedLengths TX_CS [InNetClass('TX_CS')] p1: tolerance=30 checknetsindiffpair=FALSE checkdiffpairvsdiffpair=TRUE checkxsignals=TRUE checkothers=TRUE
MatchedLengths TX_Break [InNetClass('TX_Break_out')] p2: tolerance=100 checknetsindiffpair=FALSE checkdiffpairvsdiffpair=TRUE checkxsignals=TRUE checkothers=TRUE
MatchedLengths RX_Break [InNetClass('RX_Break_out')] p3: tolerance=100 checknetsindiffpair=FALSE checkdiffpairvsdiffpair=TRUE checkxsignals=TRUE checkothers=TRUE
MatchedLengths TX [InNetClass('TX_SIGNAL')] p4: tolerance=10 checknetsindiffpair=FALSE checkdiffpairvsdiffpair=TRUE checkxsignals=TRUE checkothers=TRUE
MatchedLengths RX [InNetClass('RX_SIGNAL')] p5: tolerance=10 checknetsindiffpair=FALSE checkdiffpairvsdiffpair=TRUE checkxsignals=TRUE checkothers=TRUE
MatchedLengths MatchedLengths_RGMIITX [InNetClass('RGMII_TX')] p6: tolerance=150 checknetsindiffpair=FALSE checkdiffpairvsdiffpair=TRUE checkxsignals=TRUE checkothers=TRUE
MatchedLengths MatchedLengths_RGMIIRX [InNetClass('RGMII_RX')] p7: tolerance=200 checknetsindiffpair=FALSE checkdiffpairvsdiffpair=TRUE checkxsignals=TRUE checkothers=TRUE
MinimumAnnularRing [All] p0: scope1count=1 scope1_0_kind=Board scope1_0_value=Board scope2count=1 scope2_0_kind=Board scope2_0_value=Board commentlength=0 minimumring=3.94
MinimumAnnularRing MinimumAnnularRing_ThermalPadVias [All] p0 off: scope1count=1 scope1_0_kind=Board scope1_0_value=Board scope2count=1 scope2_0_kind=Board scope2_0_value=Board commentlength=63 minimumring=5 // Protel DXP Scope 1 Expression Was: IsVia and InAnyComponent
MinimumAnnularRing MinimumAnnularRing_ThermalPadVias [IsVia and InAnyComponent] p1: minimumring=5
MinimumAnnularRing [All] p2: minimumring=3.94
MinimumSolderMaskSliver [All] p0: scope1count=1 scope1_0_kind=Board scope1_0_value=Board scope2count=1 scope2_0_kind=Board scope2_0_value=Board commentlength=0
MinimumSolderMaskSliver MinimumSolderMaskSliver_Logo [All] p0: scope1count=1 scope1_0_kind=ComponentClass scope1_0_value=Logo scope2count=1 scope2_0_kind=ComponentClass scope2_0_value=Logo commentlength=0
MinimumSolderMaskSliver MinimumSolderMaskSliver_Logo [InComponentClass('Logo') vs InComponentClass('Logo')] p1: minsoldermaskwidth=0.7
MinimumSolderMaskSliver [All] p2: minsoldermaskwidth=3.94
NetAntennae [All] p0: scope1count=1 scope1_0_kind=Board scope1_0_value=Board scope2count=1 scope2_0_kind=Board scope2_0_value=Board commentlength=0
PasteMaskExpansion [All] p0: scope1count=1 scope1_0_kind=Board scope1_0_value=Board scope2count=1 scope2_0_kind=Board scope2_0_value=Board commentlength=0 expansion=0
PlaneClearance [All] p0: scope1count=1 scope1_0_kind=Board scope1_0_value=Board scope2count=1 scope2_0_kind=Board scope2_0_value=Board commentlength=0 clearance=8
PlaneClearance [All] p1: clearance=8
PlaneConnect "Thermal relif_1" [All] p0: scope1count=1 scope1_0_kind=ComponentClass scope1_0_value="Thermal relif" scope2count=1 scope2_0_kind=Board scope2_0_value=Board commentlength=0 planeconnectstyle=Relief reliefexpansion=20 reliefentries=4 reliefconductorwidth=15 reliefairgap=10
PlaneConnect [All] p0: scope1count=1 scope1_0_kind=Board scope1_0_value=Board scope2count=1 scope2_0_kind=Board scope2_0_value=Board commentlength=0 planeconnectstyle=Relief reliefexpansion=10 reliefentries=4 reliefconductorwidth=10 reliefairgap=10
PlaneConnect "Thermal relif_1" [InComponentClass('Thermal relif')] p1: planeconnectstyle=Relief reliefexpansion=20 reliefentries=4 reliefconductorwidth=15 reliefairgap=10
PlaneConnect [All] p2: planeconnectstyle=Relief reliefexpansion=10 reliefentries=4 reliefconductorwidth=10 reliefairgap=10
PolygonConnect "Thermal relif" [All] p0: scope1count=1 scope1_0_kind=ComponentClass scope1_0_value="Thermal relif" scope2count=1 scope2_0_kind=Board scope2_0_value=Board commentlength=0 connectstyle=Relief reliefconductorwidth=20 reliefentries=4 polygonreliefangle="90 Angle"
PolygonConnect [All] p0: scope1count=1 scope1_0_kind=Board scope1_0_value=Board scope2count=1 scope2_0_kind=Board scope2_0_value=Board commentlength=0 connectstyle=Direct reliefconductorwidth=10 reliefentries=4 polygonreliefangle="90 Angle"
PolygonConnect "Thermal relif" [InComponentClass('Thermal relif')] p1: thpad.connectstyle=Relief thpad.reliefconductorwidth=20 thpad.reliefentries=4 thpad.polygonreliefangle="90 Angle" thpad.airgapwidth=7.87 smdpad.connectstyle=Relief smdpad.reliefconductorwidth=15 smdpad.reliefentries=4 smdpad.polygonreliefangle="90 Angle" smdpad.airgapwidth=10 via.connectstyle=Relief via.reliefconductorwidth=10 via.reliefentries=4 via.polygonreliefangle="90 Angle" via.airgapwidth=10
PolygonConnect [All] p2: connectstyle=Direct reliefconductorwidth=10 reliefentries=4 polygonreliefangle="90 Angle" airgapwidth=10
RoomDefinition HSDC106E1_EVM_DP83561_64p_PowerSupply [All] p0: scope1count=1 scope1_0_kind=ComponentClass scope1_0_value=HSDC106E1_EVM_DP83561_64p_PowerSupply scope2count=1 scope2_0_kind=Board scope2_0_value=Board commentlength=0 region_x1=43727203 region_y1=45346312 region_x2=51340079 region_y2=51953181 confinementstyle=ConfineIn
RoomDefinition HSDC106E1_EVM_DP83561_64p_PowerSupply [InComponentClass('HSDC106E1_EVM_DP83561_64p_PowerSupply')] p1: confinementstyle=ConfineIn formatcopy=TRUE lockcomponents=FALSE outline 3480.72,1840.61 3622.6,1840.61 3622.6,1685.33 3958.6,1685.33 3958.6,1822.61 4109.6,1822.61 4109.6,1973.61 4242.01,1973.61 4242.01,2032.2 4109.6,2032.2 4109.6,2164.61 3977.19,2164.61 3977.19,2346.02 3639.6,2346.02 3639.6,2188.61 3480.72,2188.61
RoutingCorners [All] p0: scope1count=1 scope1_0_kind=Board scope1_0_value=Board scope2count=1 scope2_0_kind=Board scope2_0_value=Board commentlength=0 cornerstyle=45-Degree minsetback=100 maxsetback=100
RoutingLayers [All] p0: scope1count=1 scope1_0_kind=Board scope1_0_value=Board scope2count=1 scope2_0_kind=Board scope2_0_value=Board commentlength=0 top layer=Automatic mid layer 1=Automatic mid layer 2=Automatic mid layer 3=Automatic mid layer 6=Automatic bottom layer=Automatic
RoutingPriority [All] p0: scope1count=1 scope1_0_kind=Board scope1_0_value=Board scope2count=1 scope2_0_kind=Board scope2_0_value=Board commentlength=0
RoutingTopology [All] p0: scope1count=1 scope1_0_kind=Board scope1_0_value=Board scope2count=1 scope2_0_kind=Board scope2_0_value=Board commentlength=0 topology=Shortest
RoutingVias [All] p0: scope1count=1 scope1_0_kind=Board scope1_0_value=Board scope2count=1 scope2_0_kind=Board scope2_0_value=Board commentlength=0 holewidth=12 width=24 viastyle="Through Hole" minholewidth=7.87 minwidth=17.87 maxholewidth=40 maxwidth=65
RoutingVias ThermalPadVias [All] p0 off: scope1count=1 scope1_0_kind=Board scope1_0_value=Board scope2count=1 scope2_0_kind=Board scope2_0_value=Board commentlength=63 holewidth=7.87 width=19.68 viastyle="Through Hole" minholewidth=7.87 minwidth=17.87 maxholewidth=12.99 maxwidth=23.62 // Protel DXP Scope 1 Expression Was: IsVia and InAnyComponent
RoutingVias ThermalPadVias [IsVia and InAnyComponent] p1: holewidth=7.87 width=19.68 viastyle="Through Hole" minholewidth=7.87 minwidth=17.87 maxholewidth=12.99 maxwidth=23.62
RoutingVias [All] p2: holewidth=12 width=24 viastyle="Through Hole" minholewidth=7.87 minwidth=17.87 maxholewidth=40 maxwidth=65
ShortCircuit [All] p0: scope1count=1 scope1_0_kind=Board scope1_0_value=Board scope2count=1 scope2_0_kind=Board scope2_0_value=Board commentlength=0 allowed=FALSE
SilkToBoardRegionClearance [All] p0: scope1count=1 scope1_0_kind=Board scope1_0_value=Board scope2count=1 scope2_0_kind=Board scope2_0_value=Board commentlength=0
SilkToSilkClearance [All] p0: scope1count=1 scope1_0_kind=Board scope1_0_value=Board scope2count=1 scope2_0_kind=Board scope2_0_value=Board commentlength=0
SilkToSilkClearance SilkToSilkClearance_Pb-FreeLogo [All] p0 off: scope1count=1 scope1_0_kind=Board scope1_0_value=Board scope2count=1 scope2_0_kind=Board scope2_0_value=Board commentlength=120 // Protel DXP Scope 2 Expression Was: (HasFootprint('Pb-Free_Overlay_Medium') OR HasFootprint('Pb-Free_Overlay_Small'))
SilkToSilkClearance SilkToSilkClearance_Pb-FreeLogo [(HasFootprint('Pb-Free_Overlay_Medium') OR HasFootprint('Pb-Free_Overlay_Small')) vs (HasFootprint('Pb-Free_Overlay_Medium') OR HasFootprint('Pb-Free_Overlay_Small'))] p1: silktosilkclearance=0
SilkToSilkClearance [All] p2: silktosilkclearance=3
SilkToSolderMaskClearance "Silk to Solder Mask Opening" [All] p0: scope1count=1 scope1_0_kind=Board scope1_0_value=Board scope2count=1 scope2_0_kind=Board scope2_0_value=Board commentlength=0
SilkToSolderMaskClearance SilkToComponentPadClearance [All] p0 off: scope1count=1 scope1_0_kind=Board scope1_0_value=Board scope2count=1 scope2_0_kind=Board scope2_0_value=Board commentlength=87 // Protel DXP Scope 1 Expression Was: (IsPad or IsFill or IsRegion) and InAnycomponent
SilkToSolderMaskClearance SilkToComponentPadClearance [(IsPad or IsFill or IsRegion) and InAnycomponent] p1: minsilkscreentomaskgap=0 clearancetoexposedcopper=TRUE
SilkToSolderMaskClearance "Silk to Solder Mask Opening" [All] p2: minsilkscreentomaskgap=3 clearancetoexposedcopper=FALSE
SolderMaskExpansion [All] p0: scope1count=1 scope1_0_kind=Board scope1_0_value=Board scope2count=1 scope2_0_kind=Board scope2_0_value=Board commentlength=0 expansion=1.97
SolderMaskExpansion [All] p1: expansion=1.97
UnRoutedNet [All] p0: scope1count=1 scope1_0_kind=Board scope1_0_value=Board scope2count=1 scope2_0_kind=Board scope2_0_value=Board commentlength=0
UnpouredPolygon [All] p0: scope1count=1 scope1_0_kind=Board scope1_0_value=Board scope2count=1 scope2_0_kind=Board scope2_0_value=Board commentlength=0
Width [All] p0: scope1count=1 scope1_0_kind=Board scope1_0_value=Board scope2count=1 scope2_0_kind=Board scope2_0_value=Board commentlength=0 maxlimit=100 minlimit=6 preferedwidth=10
Width [All] p1: maxlimit=100 minlimit=6 preferedwidth=10 checkconnectedcopper=TRUE
15 further rules are at their usual default settings.

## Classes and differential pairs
component class HSDC106E1_EVM_DP83561_64p_Hardware: FID1 FID2 FID3 FID4 FID5 FID6 FID7 FID8 FID9 FID10 FID11 FID12 FID13 FID14 FID15 FID16 FID17 FID18 H1 H2 H3 H4 H5 H6 H7 H8 Logo1 Logo2 Logo3 Logo4 M1 M2 M3 M4 M5 M6 M7 M8 SH-J1 SH-J2 SH-J3 SH-J4 SH-J5 SH-J6 SH-J7 SH-J8
component class HSDC106E1_EVM_DP83561_64p_Breakout: J1 J2 J19 J22 R130 R132 R134 R135 R136 R201 R202 R203 R204 R205 R206 R207
component class HSDC106E1_EVM_DP83561_64p_USB: C110 C111 C112 C113 C114 C115 C116 C117 C118 C119 C120 C121 C122 C123 C124 C125 C126 C127 C128 C129 D9 J42 LD7 R174 R175 R176 R177 R178 R179 R180 R181 R182 R183 R184 R185 R186 R187 R188 R189 R190 R191 R192 R193 R194 R195 R196 R197 R198 R199 R200 U13 U14 Y3
pad class J10: J10-MH1 J10-MH2
component class HSDC106E1_EVM_DP83561_64p_MSP430: C13 C14 C15 C16 C17 C18 C19 C20 C21 C22 C23 C24 C25 D3 D4 J8 J9 J43 R35 R36 R37 R38 R39 R40 R41 R42 R43 R44 R45 R46 R47 R48 R49 R50 R51 R52 R53 R54 R55 R56 R57 R58 R59 R60 R61 R62 R63 R64 R65 R66 R67 R68 R69 R70 R71 R72 R73 R74 R75 R76 S1 S2 U2 U3 U4 Y2
component class HSDC106E1_EVM_DP83561_64p_EZFET: C1 C2 C3 C4 C5 C6 C7 C8 C9 C10 C11 C12 D1 D2 J3 R1 R2 R3 R4 R5 R6 R7 R8 R9 R10 U1 Y1
component class HSDC106E1_EVM_DP83561_64p_PHY: C26 C27 C28 C29 C30 C31 C32 C33 C34 C35 C36 C37 C38 C39 C40 C41 C42 C43 C44 C45 C46 C47 C48 C49 C51 J10 J11 J12 J13 J14 J15 J? P1 R77 R78 R79 R80 R81 R82 R83 R84 R85 R86 R87 R88 R89 R90 R91 S3 U5 VPP_TP1 XTAL1
component class HSDC106E1_EVM_DP83561_64p_PowerSupply: C50 C52 C53 C55 C56 C57 C58 C59 C60 C61 C62 C63 C64 C65 C66 C67 C68 C70 C71 C73 C74 C75 C76 C77 C78 C80 C81 C83 C84 C85 C86 C87 C88 C91 C92 C93 C94 D5 D6 D7 D8 F1 J16 J17 J18 J20 J21 J23 J24 L1 P2 Q1 Q2 Q3 Q4 R21 R22 R24 R26 R28 R30 R92 R93 R94 R95 R96 R97 R98 R99 R100 R101 R102 R103 R104 R105 R106 R108 R109 R110 R111 R273 R274 R275 R276 R282 R283 U6 U7 U8 U9 U10
component class HSDC106E1_EVM_DP83561_64p_MAC_RJ45: C54 C69 C72 C79 C82 C95 C97 C99 C101 C103 C104 C106 C107 C108 C109 J4 J5 J6 J27 R11 R12 R13 R14 R15 R16 R17 R18 R19 R20 R23 R25 R27 R29 R31 R32 R33 R34 R107 R112 R113 R114 R115 R116 R117 R118 R119 R120 R121 R122 R123 R124 R125 R126 R127 R128 R129 R131 R133 R137 R138 R139 R140 R141 R142 R143 R144 R145 R146 R258 R259 R260 R261 R262 R263 R264 R265 T1 TP1 TP2 TP3 TP4 TP5 TP6 TP7 TP8 TP9 TP10 U11 U12
component class HSDC106E1_EVM_DP83561_64p_Straps: FID1 FID2 FID3 FID4 FID5 FID6 FID7 FID8 FID9 FID10 FID11 FID12 FID13 FID14 FID15 FID16 FID17 FID18 H1 H2 H3 H4 H5 H6 H7 H8 J28 J29 J30 J31 J32 J33 J34 J35 J36 J37 J38 J39 J40 J41 LD1 LD2 LD3 LD4 LD5 LD6 Logo1 Logo2 Logo3 Logo4 M1 M2 M3 M4 M5 M6 M7 M8 R147 R148 R149 R150 R151 R152 R153 R154 R155 R156 R157 R158 R159 R160 R161 R162 R163 R164 R165 R166 R167 R168 R169 R170 R171 R172 R173 R229 R230 R231 R236 R237 R?
pad class MH: J2-MP1 J2-MP2 J2-MP3 J2-MP4 M1-1 M3-1 M5-1 M6-1 M7-1 M8-1
differential pair EZFET_PUD_N: +EZFET_PUD_P -EZFET_PUD_N
differential pair D0_N: +D0_P -D0_N
differential pair HUB_D2_N: +HUB_D2_P -HUB_D2_N
differential pair HUB_D1_N: +HUB_D1_P -HUB_D1_N
differential pair NewD2_N: +D2_P -D2_N
differential pair D1_N: +D1_P -D1_N
differential pair TD_D_cap_N: +TD_D_cap_P -TD_D_cap_N
differential pair TD_C_cap_N: +TD_C_cap_P -TD_C_cap_N
differential pair TD_B_cap_N: +TD_B_cap_P -TD_B_cap_N
differential pair TD_A_cap_N: +TD_A_cap_P -TD_A_cap_N
differential pair TD_D_RJ_N: +TD_D_RJ_P -TD_D_RJ_N
differential pair TD_C_RJ_N: +TD_C_RJ_P -TD_C_RJ_N
differential pair TD_B_RJ_N: +TD_B_RJ_P -TD_B_RJ_N
differential pair TD_A_RJ_N: +TD_A_RJ_P -TD_A_RJ_N
differential pair TD_A_mag_N: +TD_A_mag_N -TD_A_mag_P
differential pair TD_B_mag_N: +TD_B_mag_N -TD_B_mag_P
differential pair TD_C_mag_N: +TD_C_mag_N -TD_C_mag_P
differential pair TD_D_mag_N: +TD_D_mag_N -TD_D_mag_P
differential pair TD_D_x_N: +TD_D_x_P -TD_D_x_N
differential pair TD_C_x_N: +TD_C_x_P -TD_C_x_N
differential pair TD_B_x_N: +TD_B_x_P -TD_B_x_N
differential pair TD_A_x_N: +TD_A_x_P -TD_A_x_N
differential pair TD_D_N: +TD_D_P -TD_D_N
differential pair TD_C_N: +TD_C_P -TD_C_N
differential pair TD_B_N: +TD_B_P -TD_B_N
differential pair TD_A_N: +TD_A_P -TD_A_N
differential pair DM4: +DP4 -DM4
differential pair DM3: +DP3 -DM3
differential pair TD_D_mag: +TD_D_mag_P -TD_D_mag_N
differential pair TD_C_mag: +TD_C_mag_P -TD_C_mag_N
differential pair TD_B_mag: +TD_B_mag_P -TD_B_mag_N
differential pair TD_A_mag: +TD_A_mag_P -TD_A_mag_N
differential pair TD_D_x: +TD_D_x_P -TD_D_x_N
differential pair TD_D_RJ: +TD_D_RJ_P -TD_D_RJ_N
differential pair TD_D_cap: +TD_D_cap_P -TD_D_cap_N
differential pair TD_C_x: +TD_C_x_P -TD_C_x_N
differential pair TD_C_RJ: +TD_C_RJ_P -TD_C_RJ_N
differential pair TD_C_cap: +TD_C_cap_P -TD_C_cap_N
differential pair TD_B_x: +TD_B_x_P -TD_B_x_N
differential pair TD_B_RJ: +TD_B_RJ_P -TD_B_RJ_N
differential pair TD_B_cap: +TD_B_cap_P -TD_B_cap_N
differential pair TD_A_x: +TD_A_x_P -TD_A_x_N
differential pair TD_A_RJ: +TD_A_RJ_P -TD_A_RJ_N
differential pair TD_A_cap: +TD_A_cap_P -TD_A_cap_N
differential pair D0: +D0_P -D0_N
differential pair D1: +D1_P -D1_N
differential pair D2: +D2_P -D2_N
differential pair EZFET_PUD: +EZFET_PUD_P -EZFET_PUD_N
differential pair HUB_D1: +HUB_D1_P -HUB_D1_N
differential pair HUB_D2: +HUB_D2_P -HUB_D2_N
differential pair TARGET_D: +TARGET_D_P -TARGET_D_N
differential pair " ": +USB_P -USB_N

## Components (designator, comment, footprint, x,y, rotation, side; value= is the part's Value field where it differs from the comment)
C1 "CL05B104KO5NNNC" 0402#1 5159.6,4903.61 r0 bottom
C2 "885012005043" 0402#1 5037.6,5113.61 r180 bottom
C3 "885012005043" 0402#1 5037.6,5025.7 r180 top
C4 "CL05C360JB5NNNC" 0402#1 5232.1,5255.55 r270 top
C5 "CL05C360JB5NNNC" 0402#1 5467.6,5281.61 r90 top
C6 "CL10A224KB8NNNC" 0603 5319.6,5077.61 r270 bottom
C7 "CGA3E3X7R1H474K080AB" 0603 5172.6,4772.61 r90 bottom
C8 "GRM1555C1H102JA01D" 0402#1 5193,5136.7 r0 top
C9 "CL10A224KB8NNNC" 0603 5378.6,5076.61 r270 bottom
C10 "TPSD106K035R0125" 7343-31 5000.6,4700.61 r270 bottom
C11 "CL05B104KO5NNNC" 0402#1 5060.6,4859.7 r180 top
C12 "CL05B104KO5NNNC" 0402#1 5465.6,4905.61 r180 bottom
C13 "GCM155R71H104KE02D" 0402#1 3507.2,4470.61 r270 top
C14 "GCM155R71H104KE02D" 0402#1 4114.6,4234.61 r270 top
C15 "CL05C360JB5NNNC" 0402#1 4720.98,4822.61 r0 top
C16 "CL05C360JB5NNNC" 0402#1 4721.6,4995.61 r180 bottom
C17 "C0603C224Z4VACTU" 0603 4507.6,4881.61 r180 bottom
C18 "GCM188R71C474KA55D" 0603 4083.6,5180.11 r270 bottom
C19 "C1608X5R1V475K080AC" 0603 4507.26,4764.18 r0 bottom
C20 "C0603C224Z4VACTU" 0603 4507.26,4823.24 r180 bottom
C21 "TPSD106K035R0125" 7343-31 4155.6,5445.61 r0 top
C22 "C0402C104K8RACTU" 0402#1 4171.79,5306.61 r0 top
C23 "C0402C104K8RACTU" 0402#1 4171.79,5259.61 r0 top
C24 "C0402C104K8RACTU" 0402#1 4223,5259.61 r180 bottom
C25 "GRM1555C1H102JA01D" 0402#1 5343,4247.61 r0 bottom
C26 "CMP-0006259-2" 0402#1 3546.6,2065.61 r0 bottom
C27 "C1005X5R1C105K050BC" 0402#1 3547.6,1971.61 r0 bottom
C28 "CMP-0006259-2" 0402#1 3547.6,2018.61 r0 bottom
C29 "CMP-0006259-2" 0402#1 4081.44,2021.76 r180 bottom
C30 "CMP-0006259-2" 0402#1 4080.6,2068.61 r180 bottom
C31 "CMP-0006259-2" 0402#1 3928.42,2349.36 r0 bottom
C32 "CMP-0006259-2" 0402#1 3928.42,2302.41 r0 bottom
C33 "CMP-0006259-2" 0402#1 3545.6,2113.61 r0 bottom
C34 "CMP-0006259-2" 0402#1 3547.79,1925.61 r0 bottom
C35 "CMP-0006259-2" 0402#1 3548.6,1880.61 r0 bottom
C36 "CMP-0006259-2" 0402#1 3615.74,2243.98 r270 bottom
C37 "CMP-0006259-2" 0402#1 3663.6,2244.61 r270 bottom
C38 "CMP-0006259-2" 0402#1 3547.24,1786.1 r0 bottom
C39 "CMP-0006259-2" 0402#1 3547.24,1834.92 r0 bottom
C40 "CMP-0006259-2" 0402#1 3771.75,1712.95 r180 bottom
C41 "CMP-0006259-2" 0402#1 3770.9,1757.95 r180 bottom
C42 "CMP-0006259-2" 0402#1 4081.44,1973.7 r180 bottom
C43 "CMP-0006259-2" 0402#1 4081.6,1927.61 r180 bottom
C44 "CMP-0006259-2" 0402#1 3752.6,2242.61 r270 bottom
C45 "CMP-0006259-2" 0402#1 3799.6,2242.61 r270 bottom
C46 "CMP-0006674-2" 0402#1 354.5,769.63 r270 bottom
C47 "GRM21BC80G476ME15L" 0805_HV 189.29,667.8 r270 bottom
C48 "CMP-0007116-4" 0603 3835.97,1357.3 r270 bottom
C49 "CMP-0007116-4" 0603 4178.47,1322.8 r180 bottom
C50 "CMP-0009155-2" 1210_280 1000,4917.7 r0 top
C51 "GRM1555C1H470FA01D" 0402#1 3426.41,1829.61 r90 top
C52 "CMP-0009155-2" 1210_280 995,5080.7 r270 top
C53 "GRM216R61C105KA88D" 0805_HV 996.6,5079.61 r270 bottom
C54 "CMP-0006850-4" 0603 1589,1749 r180 bottom
C55 "CMP-0006324-2" 0402#1 1079.6,5084.61 r270 bottom
C56 "GCM155R71H104KE02D" 0402#1 701.6,5840.57 r270 top
C57 "T491D227K006AT" 7343-31 1217.6,5661.61 r270 top
C58 "CMP-0006850-4" 0603 1120.1,5758.24 r90 bottom
C59 "CMP-0006303-2" 0402#1 1099.6,5764.74 r90 top
C60 "C3216X7R1V106M160AC" 1206_190 1043.6,5733.95 r270 bottom
C61 "CMP-0006850-4" 0603 1043.6,5755.61 r90 top
C62 "CGA3E1X7R1V105K080AC" 0603 609.1,5913.61 r180 top
C63 "EMVE500ADA101MHA0G" CAPSMT_62_HA0 674.6,5505.61 r270 top
C64 "CGA6P3X7R1H475K250AB" 1210_280 553.86,5714.61 r270 bottom
C65 "CGA3E3X7R1H224K080AB" 0603 530.6,5747.61 r270 top
C66 "CGA6P3X7R1H475K250AB" 1210_280 441.6,5729.61 r270 top
C67 "CGA3E3X7R1H224K080AB" 0603 640.22,5737.58 r270 bottom
C68 "CMP-0009155-2" 1210_280 1011,4365.7 r0 top
C69 "CMP-0006850-4" 0603 1610.47,1873.53 r180 bottom
C70 "CMP-0009155-2" 1210_280 962,4529.7 r270 top
C71 "GRM216R61C105KA88D" 0805_HV 963.6,4536.61 r270 bottom
C72 "CMP-0006850-4" 0603 1605,2040 r180 bottom
C73 "CMP-0006324-2" 0402#1 1048,4551.61 r270 bottom
C74 "CMP-0009154-2" 1210_280 1872.6,4585.65 r90 bottom
C75 "CMP-0009154-2" 1210_280 2025.6,5061.61 r90 bottom
C76 "CMP-0009154-2" 1210_280 2026.6,5246.61 r270 bottom
C77 "CMP-0009154-2" 1210_280 1884.6,3441.61 r90 bottom
C78 "CMP-0009155-2" 1210_280 1017,3846.7 r0 top
C79 "CMP-0006850-4" 0603 1599,2228 r180 bottom
C80 "CMP-0009155-2" 1210_280 963,4007.7 r270 top
C81 "GRM216R61C105KA88D" 0805_HV 966.6,4007.61 r270 bottom
C82 "C0402C103J5RACTU" 0402#2 537.6,1729.61 r180 top
C83 "CMP-0006324-2" 0402#1 1046.6,4012.61 r270 bottom
C84 "CMP-0009154-2" 1210_280 1887.6,3931.61 r90 bottom
C85 "C3216X7R1V106M160AC" 1206_190 343,3444.09 r90 bottom
C86 "C3216X7R1V106M160AC" 1206_190 751,3513.7 r90 bottom
C87 "CL10B104KO8NNNC" 0603 833,3486.7 r90 bottom
C88 "CMP-0006850-4" 0603 832,3487.7 r270 top
C91 "CMP-0011720-2" 7343-31 294.6,3492.09 r90 top
C92 "0805YD105KAT2A" 0805_HV 437.5,3434.7 r270 bottom
C93 "CC0805ZRY5V6BB475" 0805_HV 437.5,3434.7 r90 top
C94 "CMP-0007116-4" 0603 805.6,3308.61 r0 top
C95 "GRM155R61A333KA01D" 0402#1 2152.6,2299.61 r180 bottom
C97 "GRM155R61A333KA01D" 0402#1 2152.6,2252.61 r180 bottom
C99 "GRM155R61A333KA01D" 0402#1 2148.19,2150.98 r180 bottom
C101 "GRM155R61A333KA01D" 0402#1 2148.02,2102.61 r180 bottom
C103 "GRM155R61A333KA01D" 0402#1 2149.6,1974.61 r180 bottom
C104 "GRM155R61A333KA01D" 0402#1 2149.6,1927.61 r180 bottom
C106 "GRM155R61A333KA01D" 0402#1 2148.6,1825.61 r180 bottom
C107 "GRM155R61A333KA01D" 0402#1 2148.6,1778.61 r180 bottom
C108 "CMP-0009295-2" 1812_254 382,1502 r90 bottom
C109 "CMP-0009295-2" 1812_254 382,2511.64 r270 bottom
C110 "GRM155R6YA105ME11D" 0402#1 4167.6,5829.61 r180 bottom
C111 "GRM188R6YA106MA73D" 0603 4157,5830.7 r180 top
C112 "GRM155C81C225KE11D" 0402#1 4161.6,5724.26 r270 top
C113 "GRM155C81C225KE11D" 0402#1 4161.6,5724.26 r270 bottom
C114 "GRM188R6YA106MA73D" 0603 4107.6,5712.61 r270 top
C115 "06031C471JAT2A" 0603 4263.6,5602.11 r270 top
C116 "293D475X9035D2TE3" 7343-31 5145.6,5829.61 r0 bottom
C117 "C0402C104K8RACTU" 0402#1 5151.04,5964.5 r180 top
C118 "C1005NP01H220J050BA" 0402#1 5104,5729 r180 top
C119 "C1005NP01H220J050BA" 0402#1 5200,5687 r0 top
C120 "C1005NP01H220J050BA" 0402#1 4896.6,5552.61 r180 bottom
C121 "C1005NP01H220J050BA" 0402#1 4895.98,5596.61 r180 bottom
C122 "C0402C100K4GACTU" 0402#1 4782.6,4721.61 r0 top
C123 "C0402C100K4GACTU" 0402#1 4782.6,4775.61 r0 top
C124 "C1005NP01H220J050BA" 0402#1 4896.41,5468.5 r180 bottom
C125 "C1005NP01H220J050BA" 0402#1 4896.41,5509.5 r180 bottom
C126 "CL05B104KO5NNNC" 0402#1 5001,5727.7 r180 top
C127 "C0402C100K4GACTU" 0402#1 4636.24,5471.7 r180 bottom
C128 "C0402C100K4GACTU" 0402#1 4637.62,5516.7 r180 bottom
C129 "CL05B104KO5NNNC" 0402#1 4925,5700.7 r90 top
D1 "150060RS75000" WL-SMCW_RED 5180.28,4565.7 r0 top
D2 "150060VS55040" WL-SMCD-0603 5299.09,4560.04 r180 top
D3 "HSMF-C165" HSMF-C165_RG 3703.13,5150.01 r180 top
D4 "HSMF-C165" HSMF-C165_RG 3704.57,5044.86 r180 top
D5 "CMP-0002917-2" QTLP630C_Green 1448.6,4080.61 r90 top
D6 "CMP-0002917-2" QTLP630C_Green 1458,4587.7 r90 top
D7 "CMP-0002917-2" QTLP630C_Green 1460,5059.7 r90 top
D8 "CMP-0002917-2" QTLP630C_Green 1478.6,3501.8 r90 top
D9 "NRVBA160T3G" SMA 4802.6,5830.61 r0 bottom
F1 "F0603E3R00FSTR" 0603 386.05,5816.89 r180 bottom
FID1 "CMP-0077181-1" Fiducial10-30 6108.36,310.06 r90 top
FID2 "CMP-0077181-1" Fiducial10-30 519,6038.7 r90 top
FID3 "CMP-0077181-1" Fiducial10-30 5811,5969 r90 top
FID4 "CMP-0077181-1" Fiducial10-30 7641,1993 r90 top
FID5 "CMP-0077181-1" Fiducial10-30 8445,1981 r90 top
FID6 "CMP-0077181-1" Fiducial10-30 8410,-52 r90 top
FID7 "CMP-0077181-1" Fiducial10-30 7319,-90 r90 top
FID8 "CMP-0077181-1" Fiducial10-30 7373,1972 r90 top
FID9 "CMP-0077181-1" Fiducial10-30 6630.87,1975.12 r90 top
FID10 "CMP-0077181-1" Fiducial10-30 6630.87,1975.12 r90 bottom
FID11 "CMP-0077181-1" Fiducial10-30 7373,1972 r90 bottom
FID12 "CMP-0077181-1" Fiducial10-30 7641,1993 r90 bottom
FID13 "CMP-0077181-1" Fiducial10-30 8445,1981 r90 bottom
FID14 "CMP-0077181-1" Fiducial10-30 8410,-52 r90 bottom
FID15 "CMP-0077181-1" Fiducial10-30 7319,-90 r90 bottom
FID16 "CMP-0077181-1" Fiducial10-30 6105,314 r90 bottom
FID17 "CMP-0077181-1" Fiducial10-30 5811,5970 r90 bottom
FID18 "CMP-0077181-1" Fiducial10-30 517,6034 r90 bottom
H1 "1902C" Keystone_1902C 3025,-10 r180 bottom
H2 "1902C" Keystone_1902C 0,0 r180 bottom
H3 "1902C" Keystone_1902C 0,1348.16 r180 bottom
